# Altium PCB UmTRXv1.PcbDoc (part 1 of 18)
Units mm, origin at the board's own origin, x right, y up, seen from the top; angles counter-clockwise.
Board outline 172 x 113 mm, 6 copper layers (Top Layer, GND, MidLayer1, Mid-Layer 2, InternalPlane2, Bottom Layer); 766 components, 613 nets, 3008 pads, 1360 vias.
Unrouted connection lines stored in the file: 2.
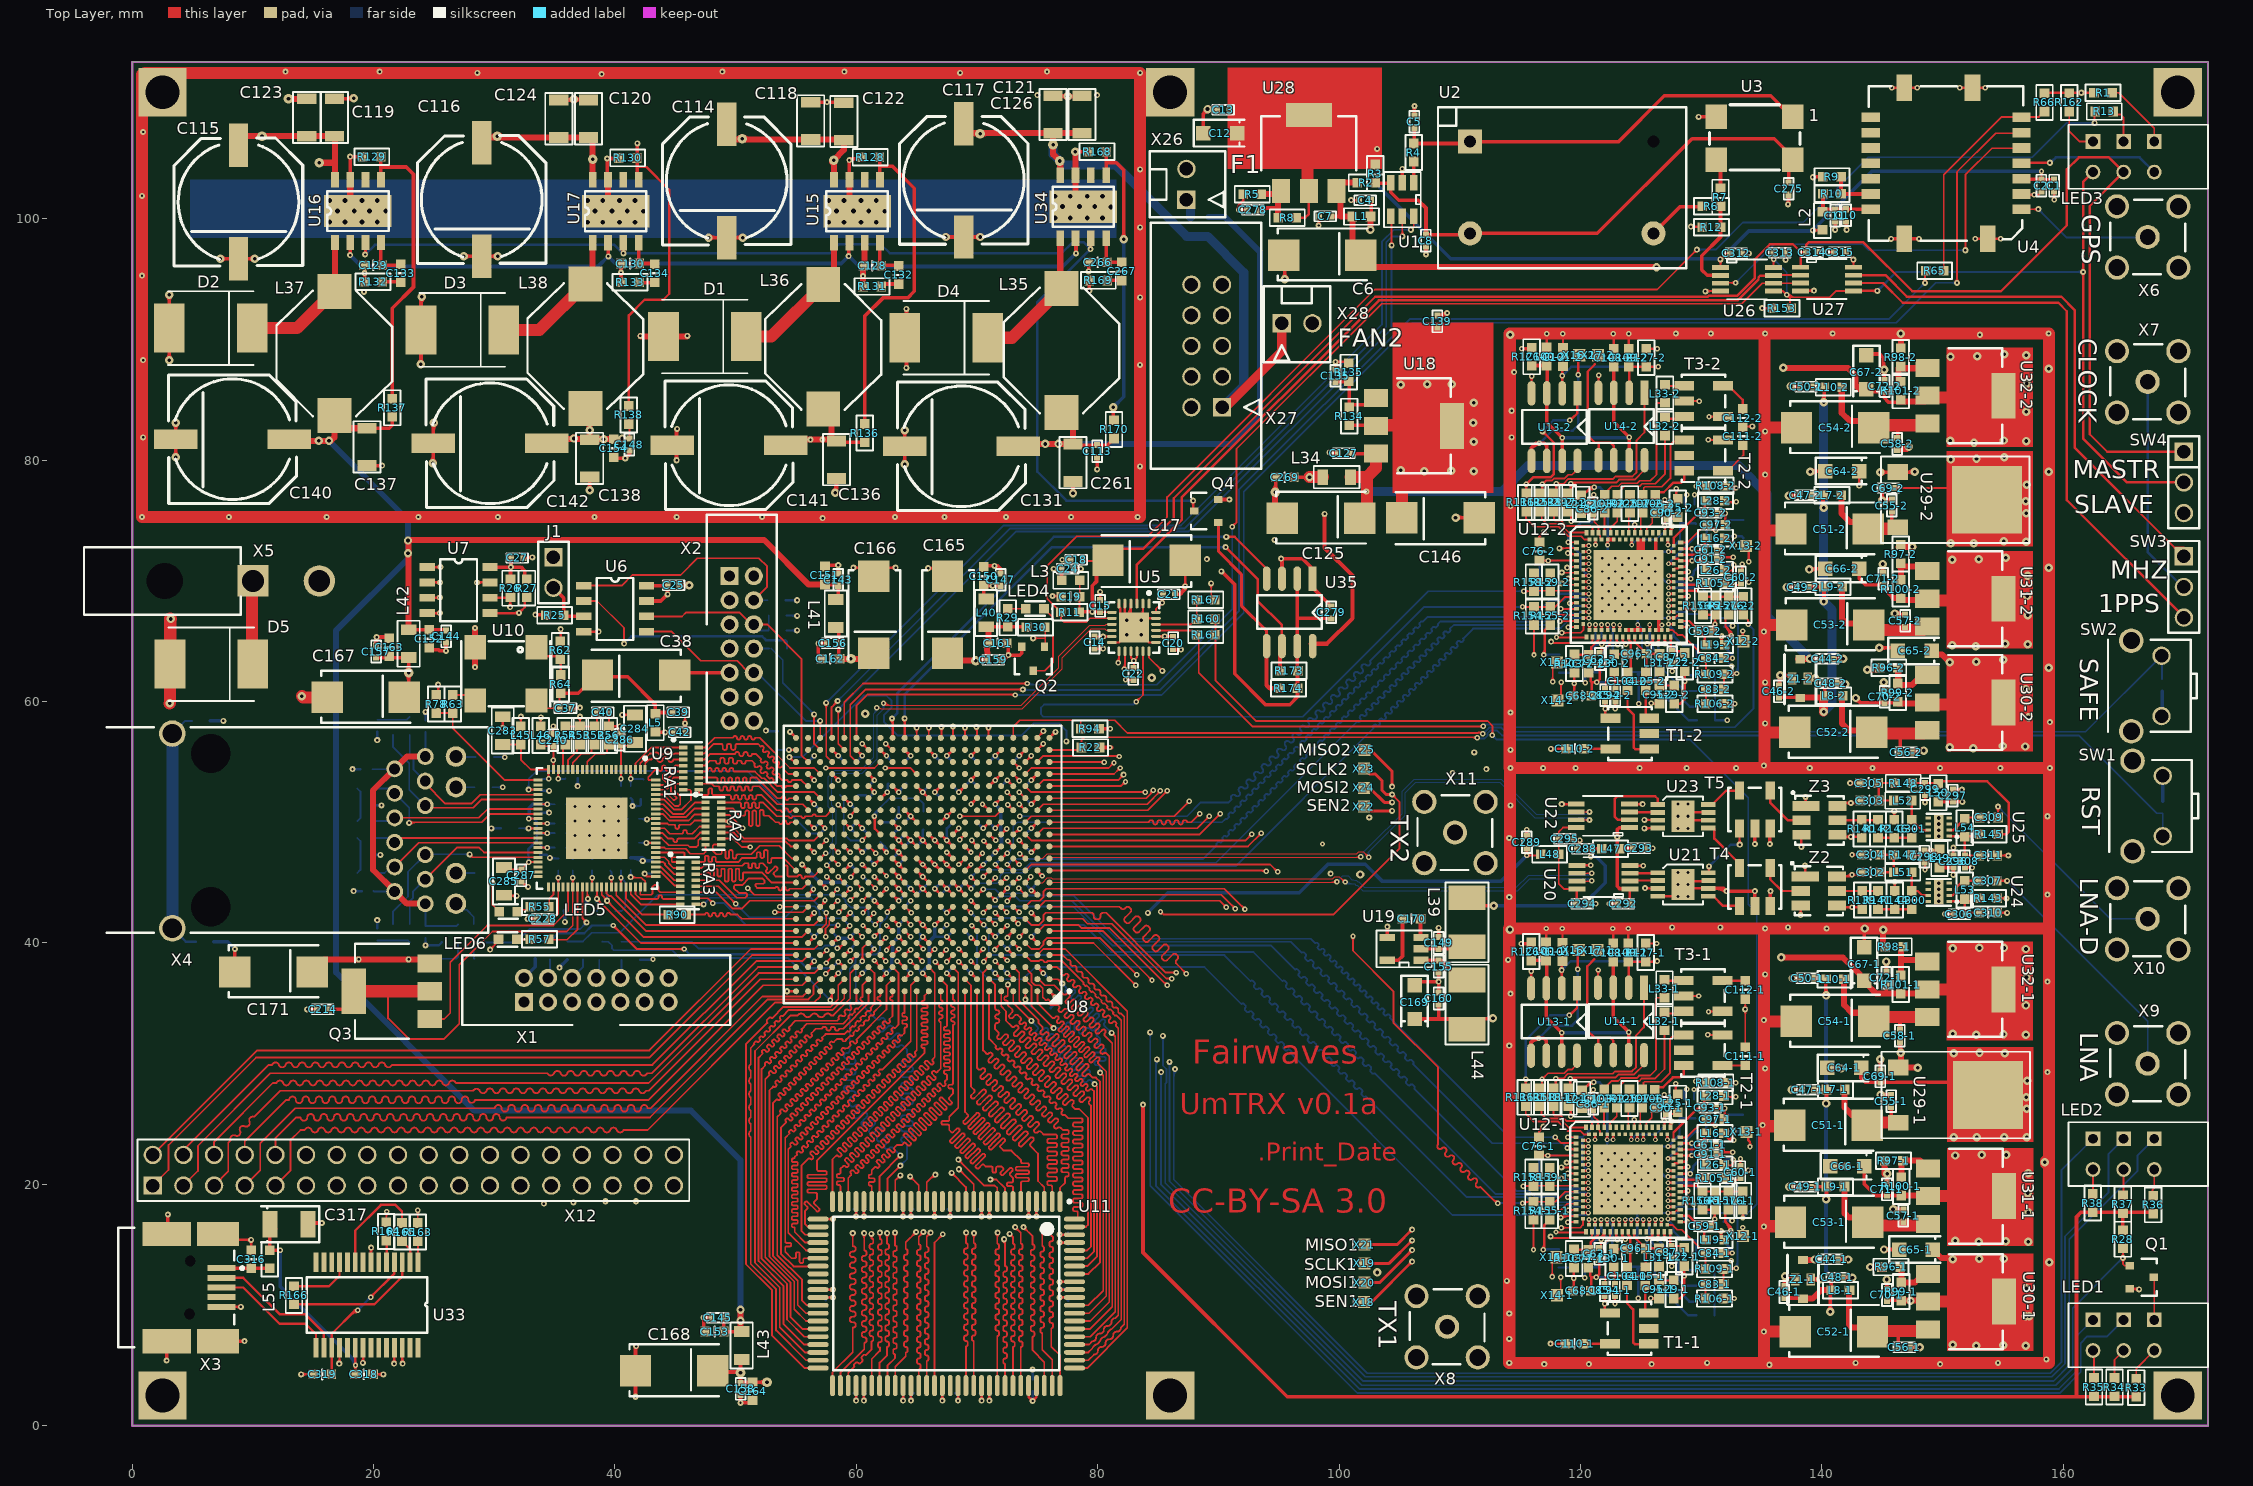
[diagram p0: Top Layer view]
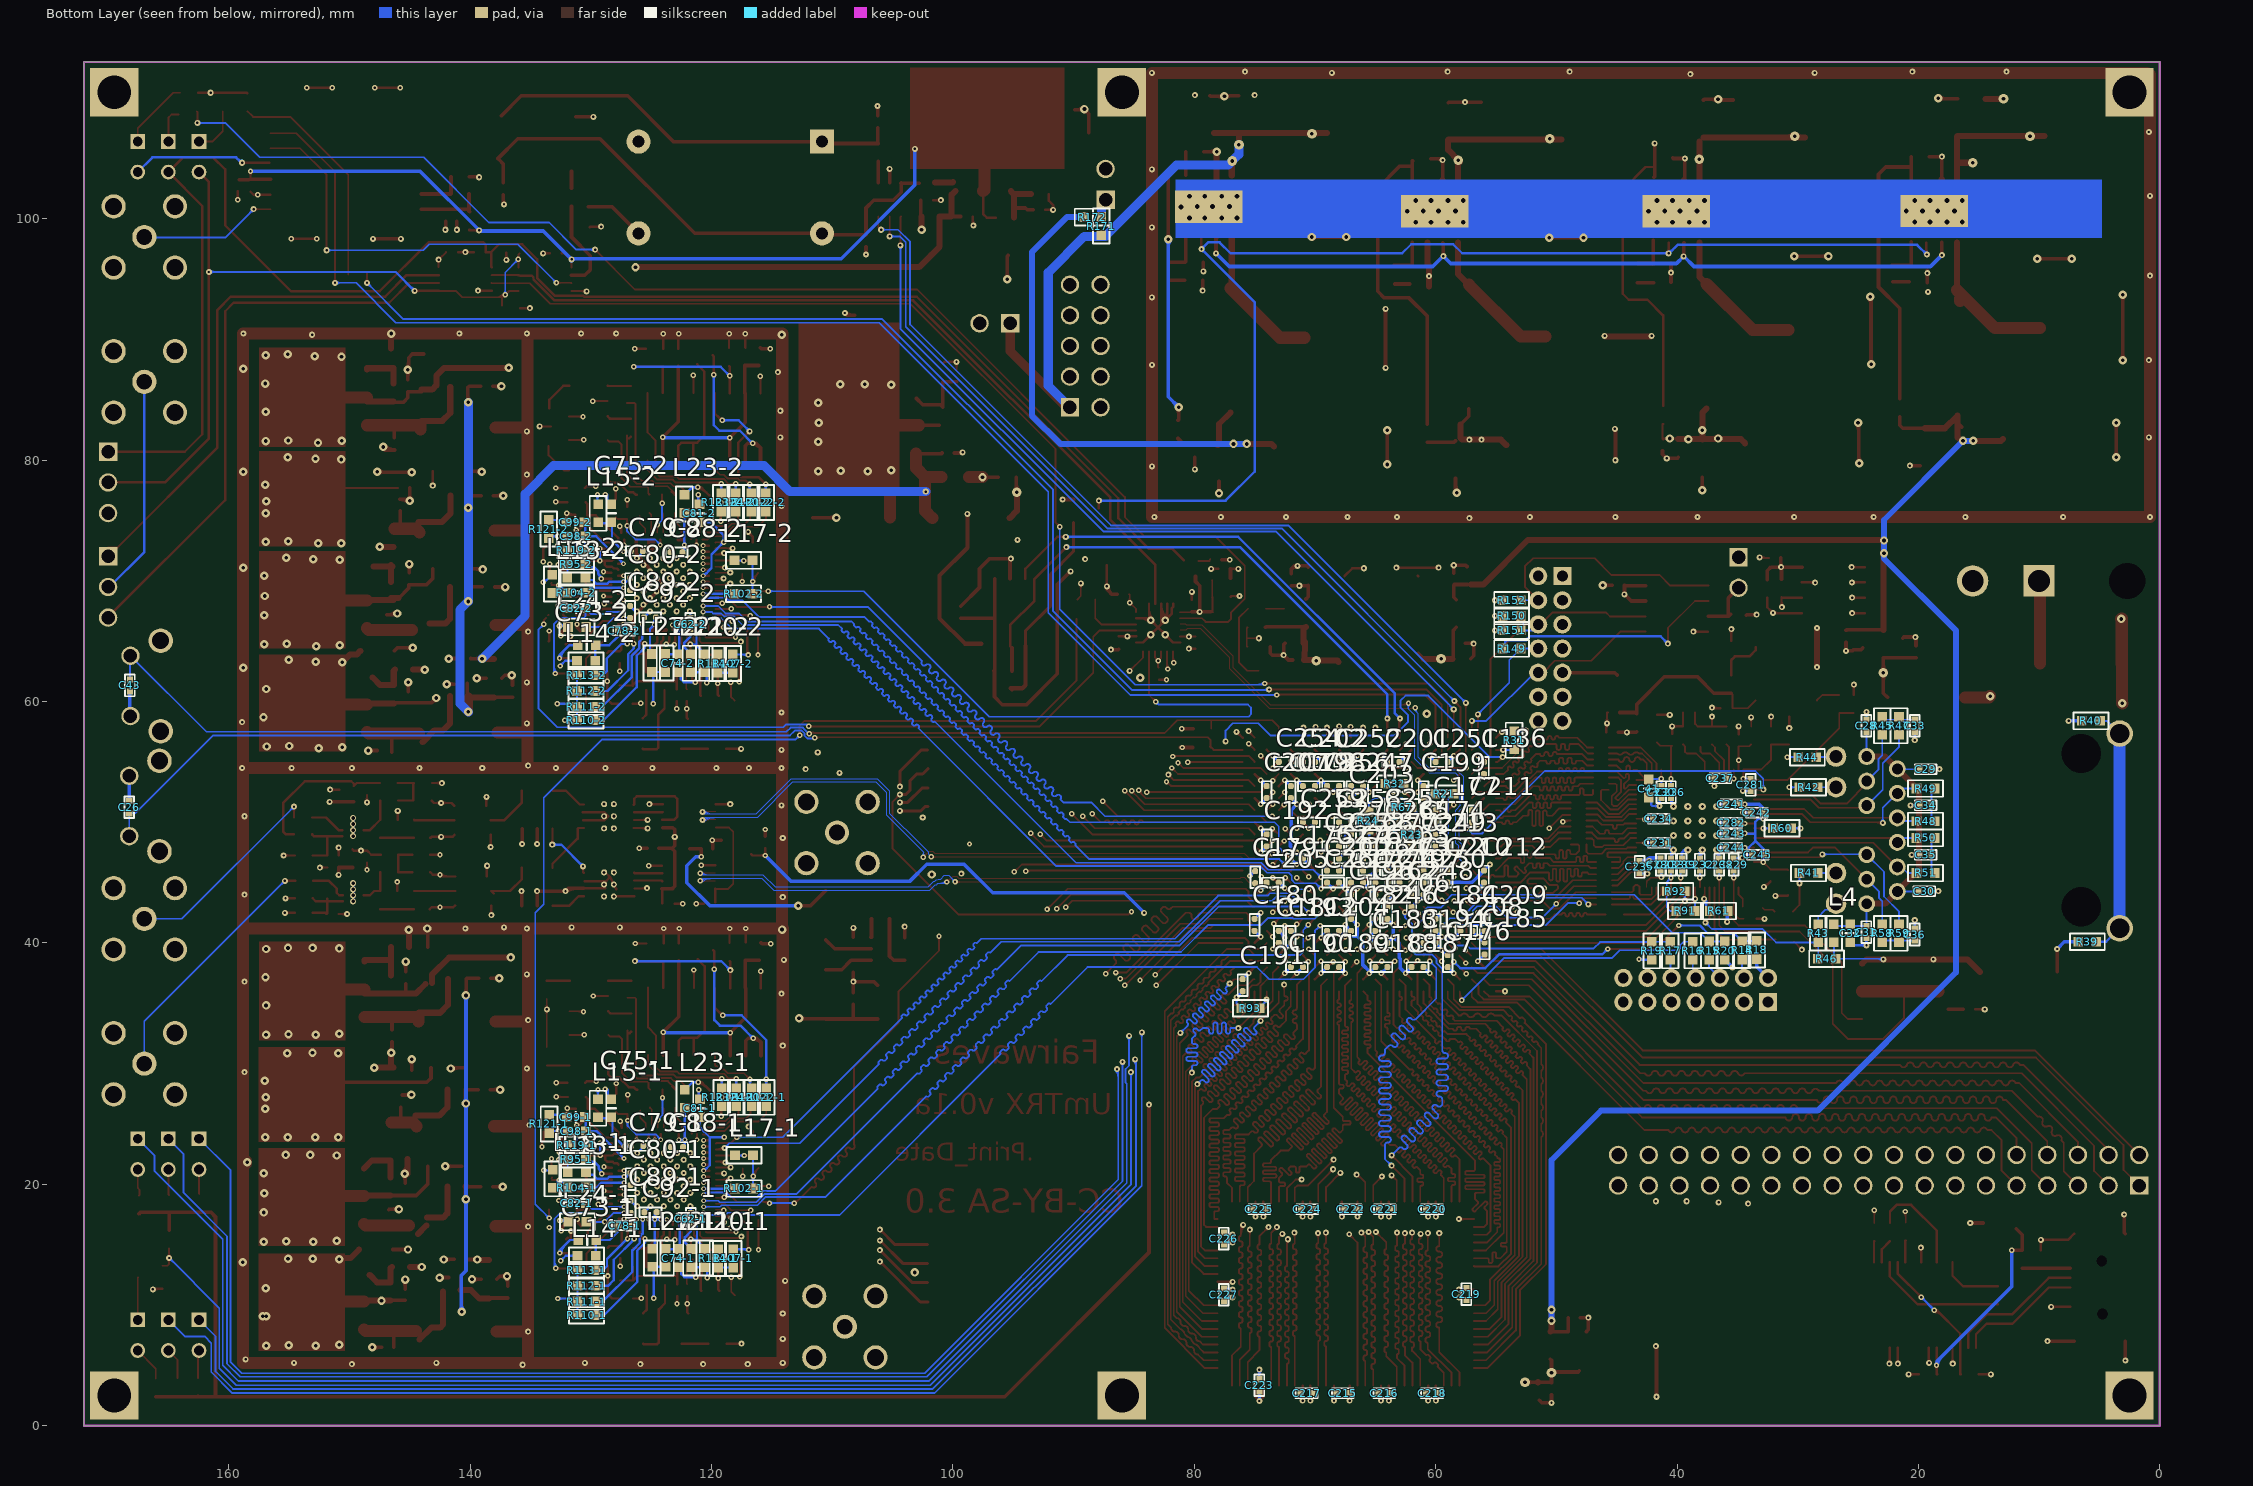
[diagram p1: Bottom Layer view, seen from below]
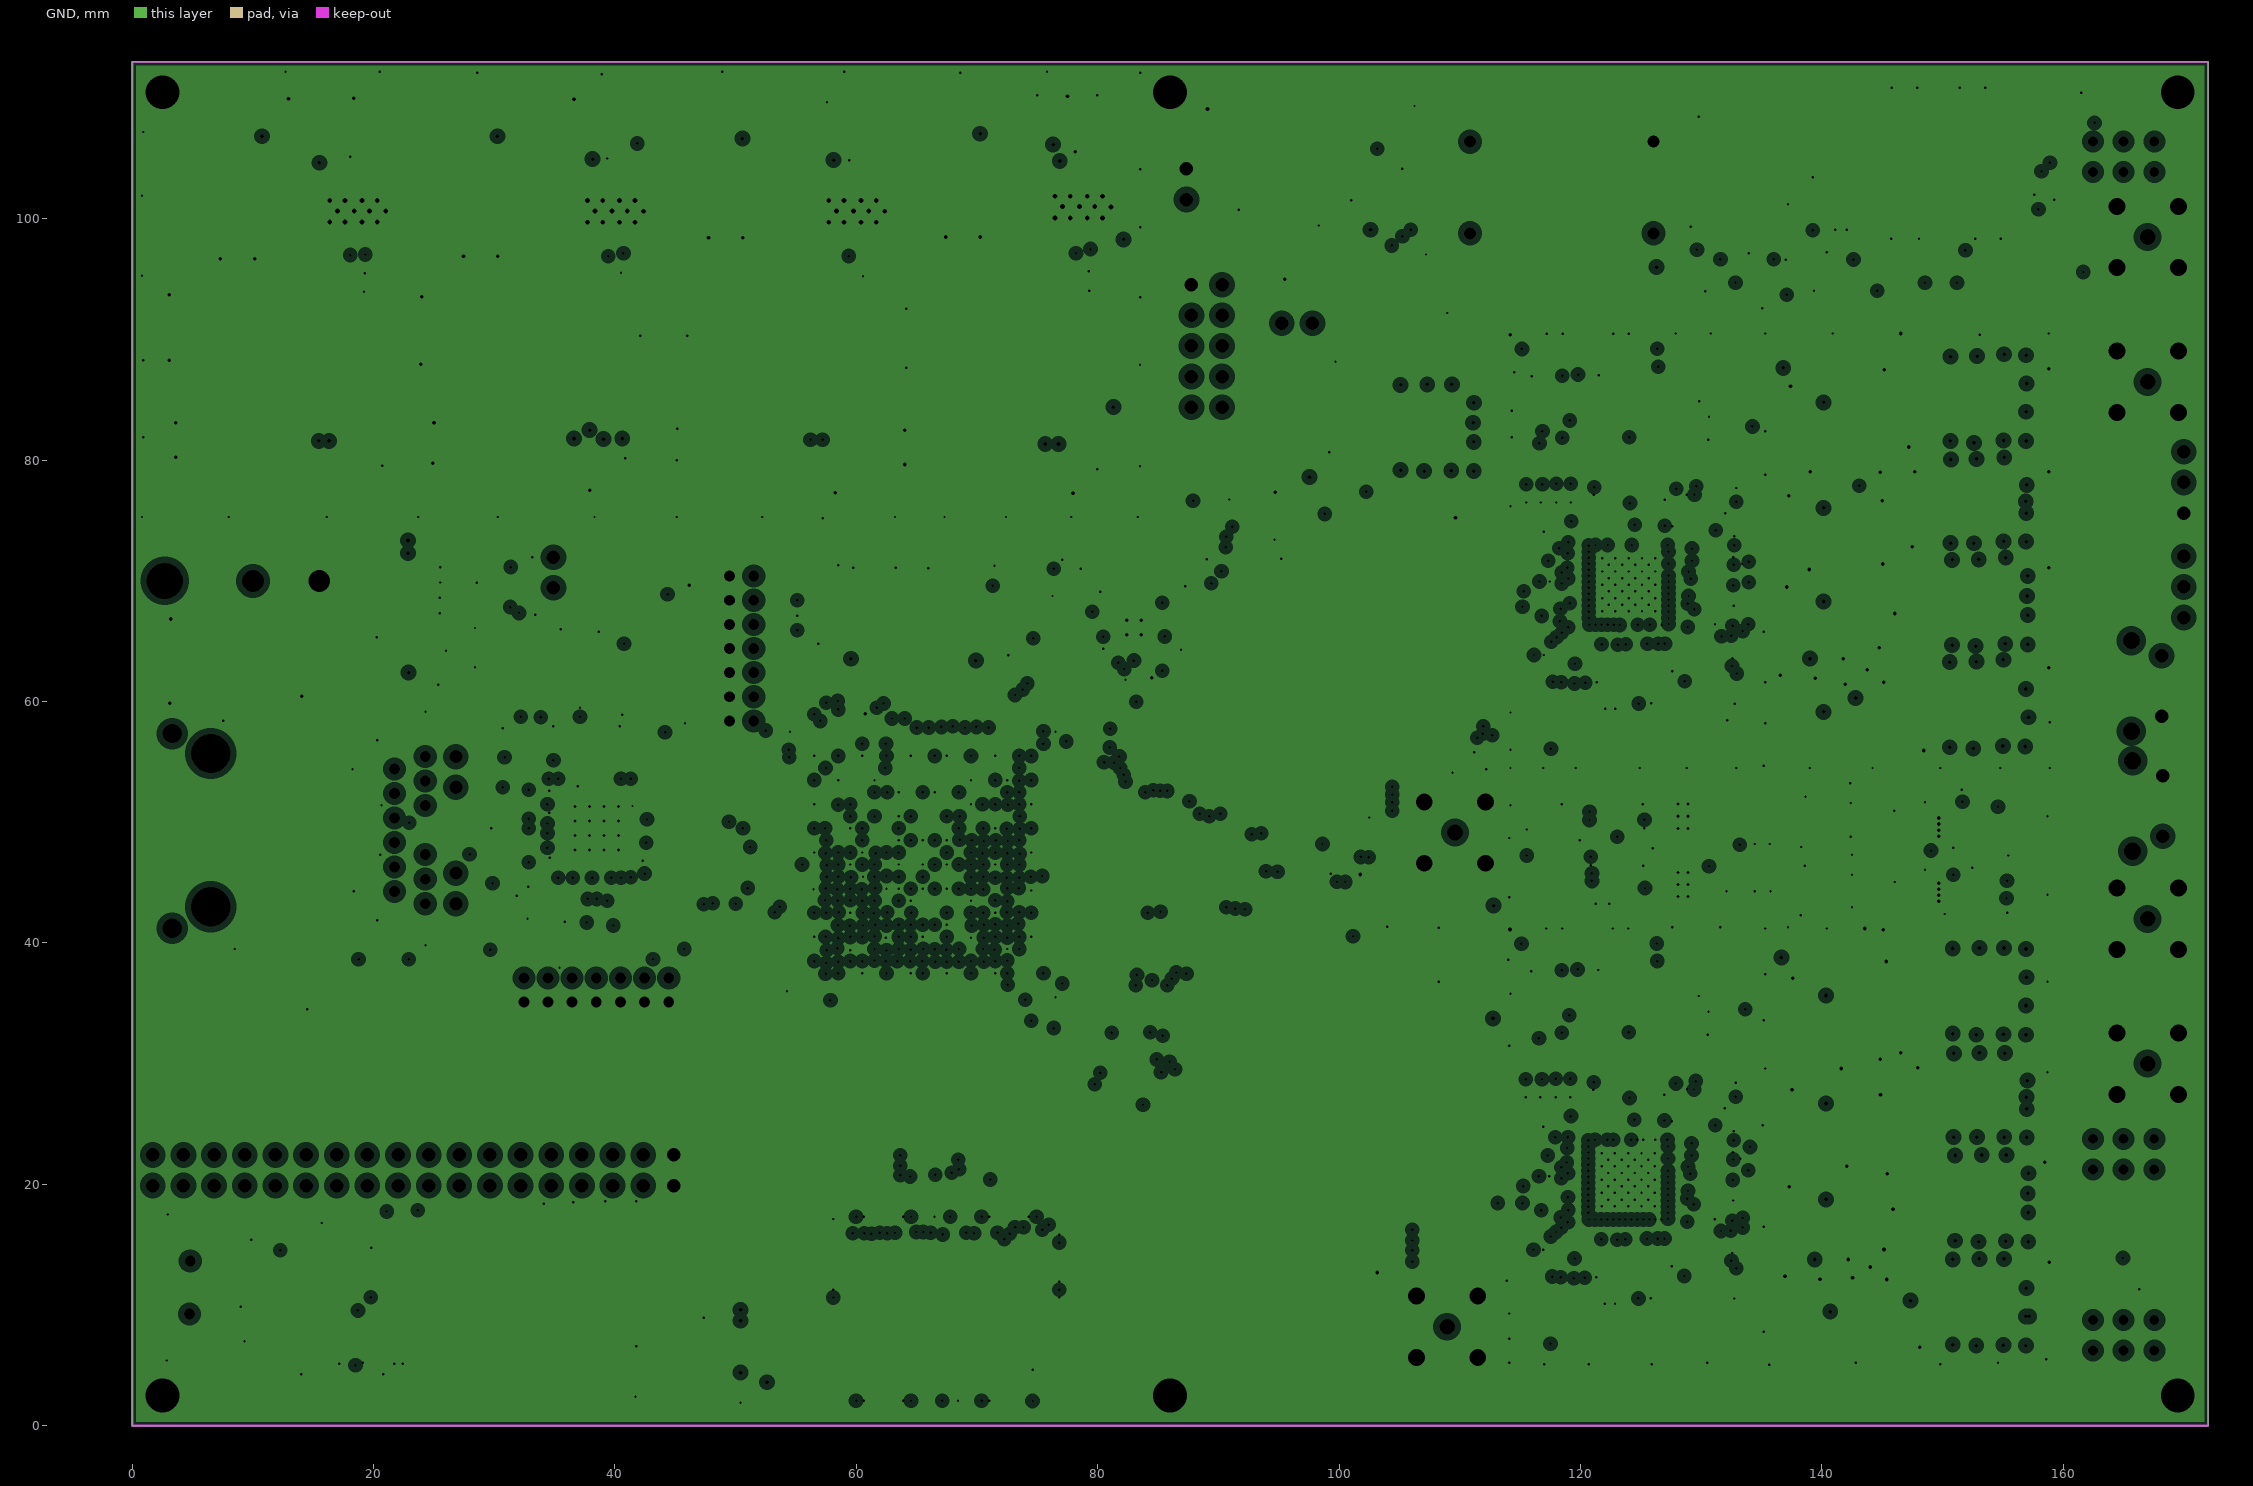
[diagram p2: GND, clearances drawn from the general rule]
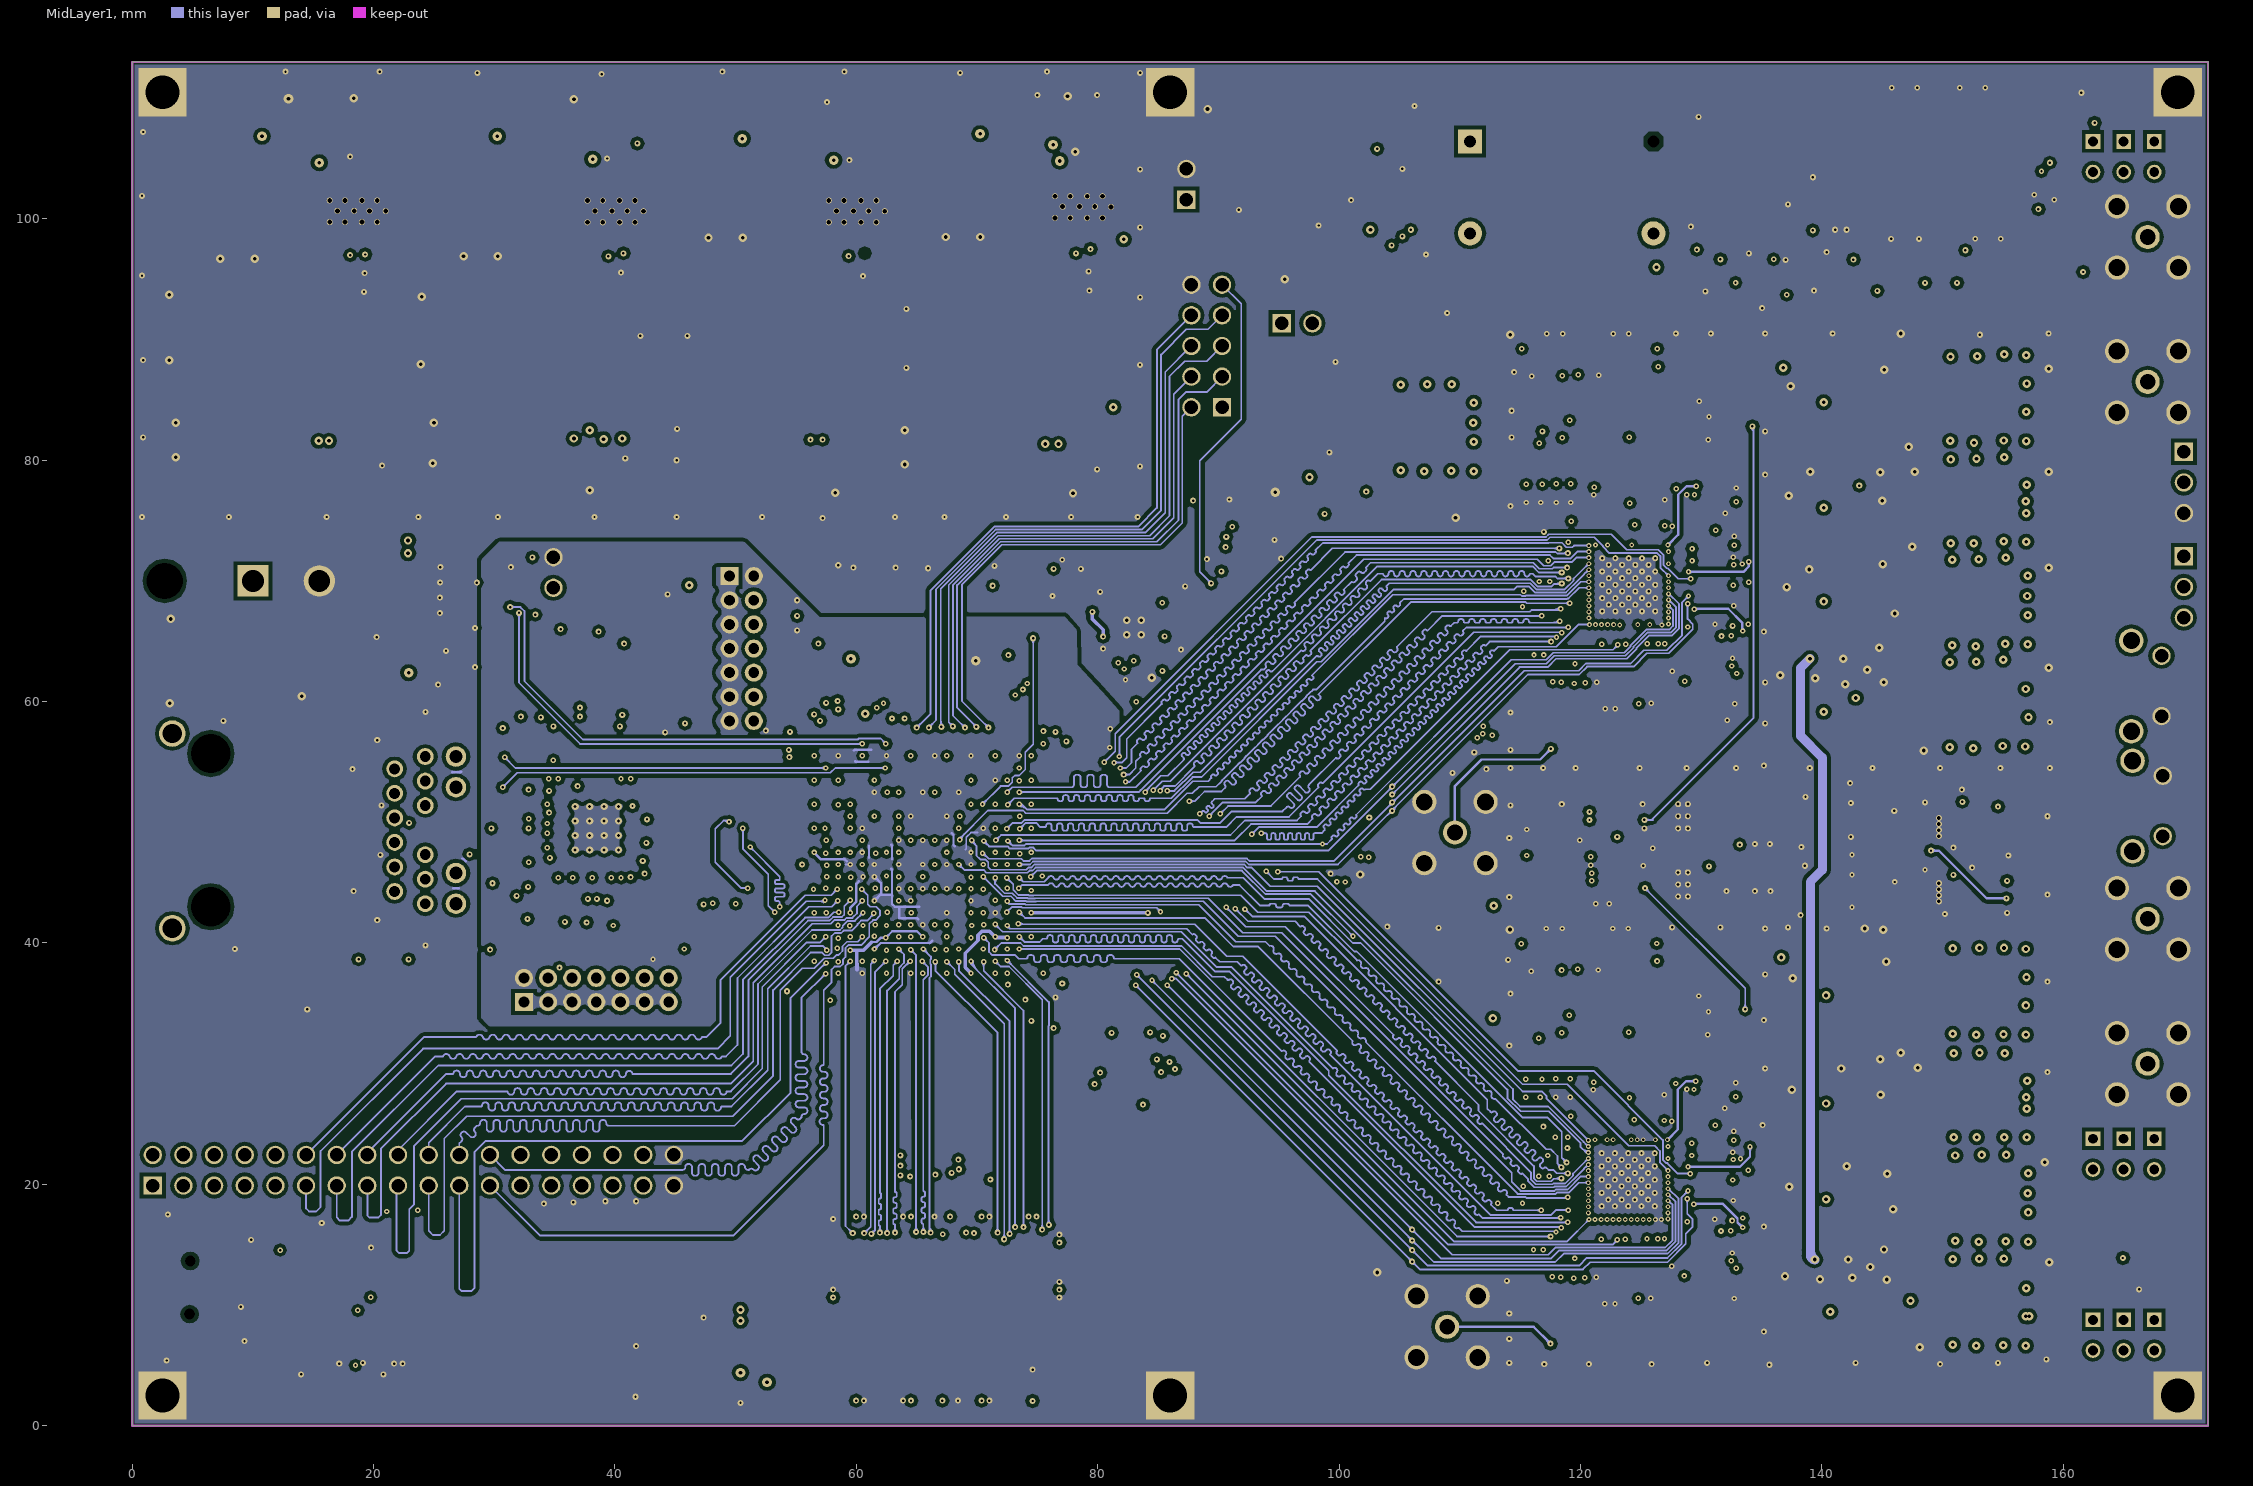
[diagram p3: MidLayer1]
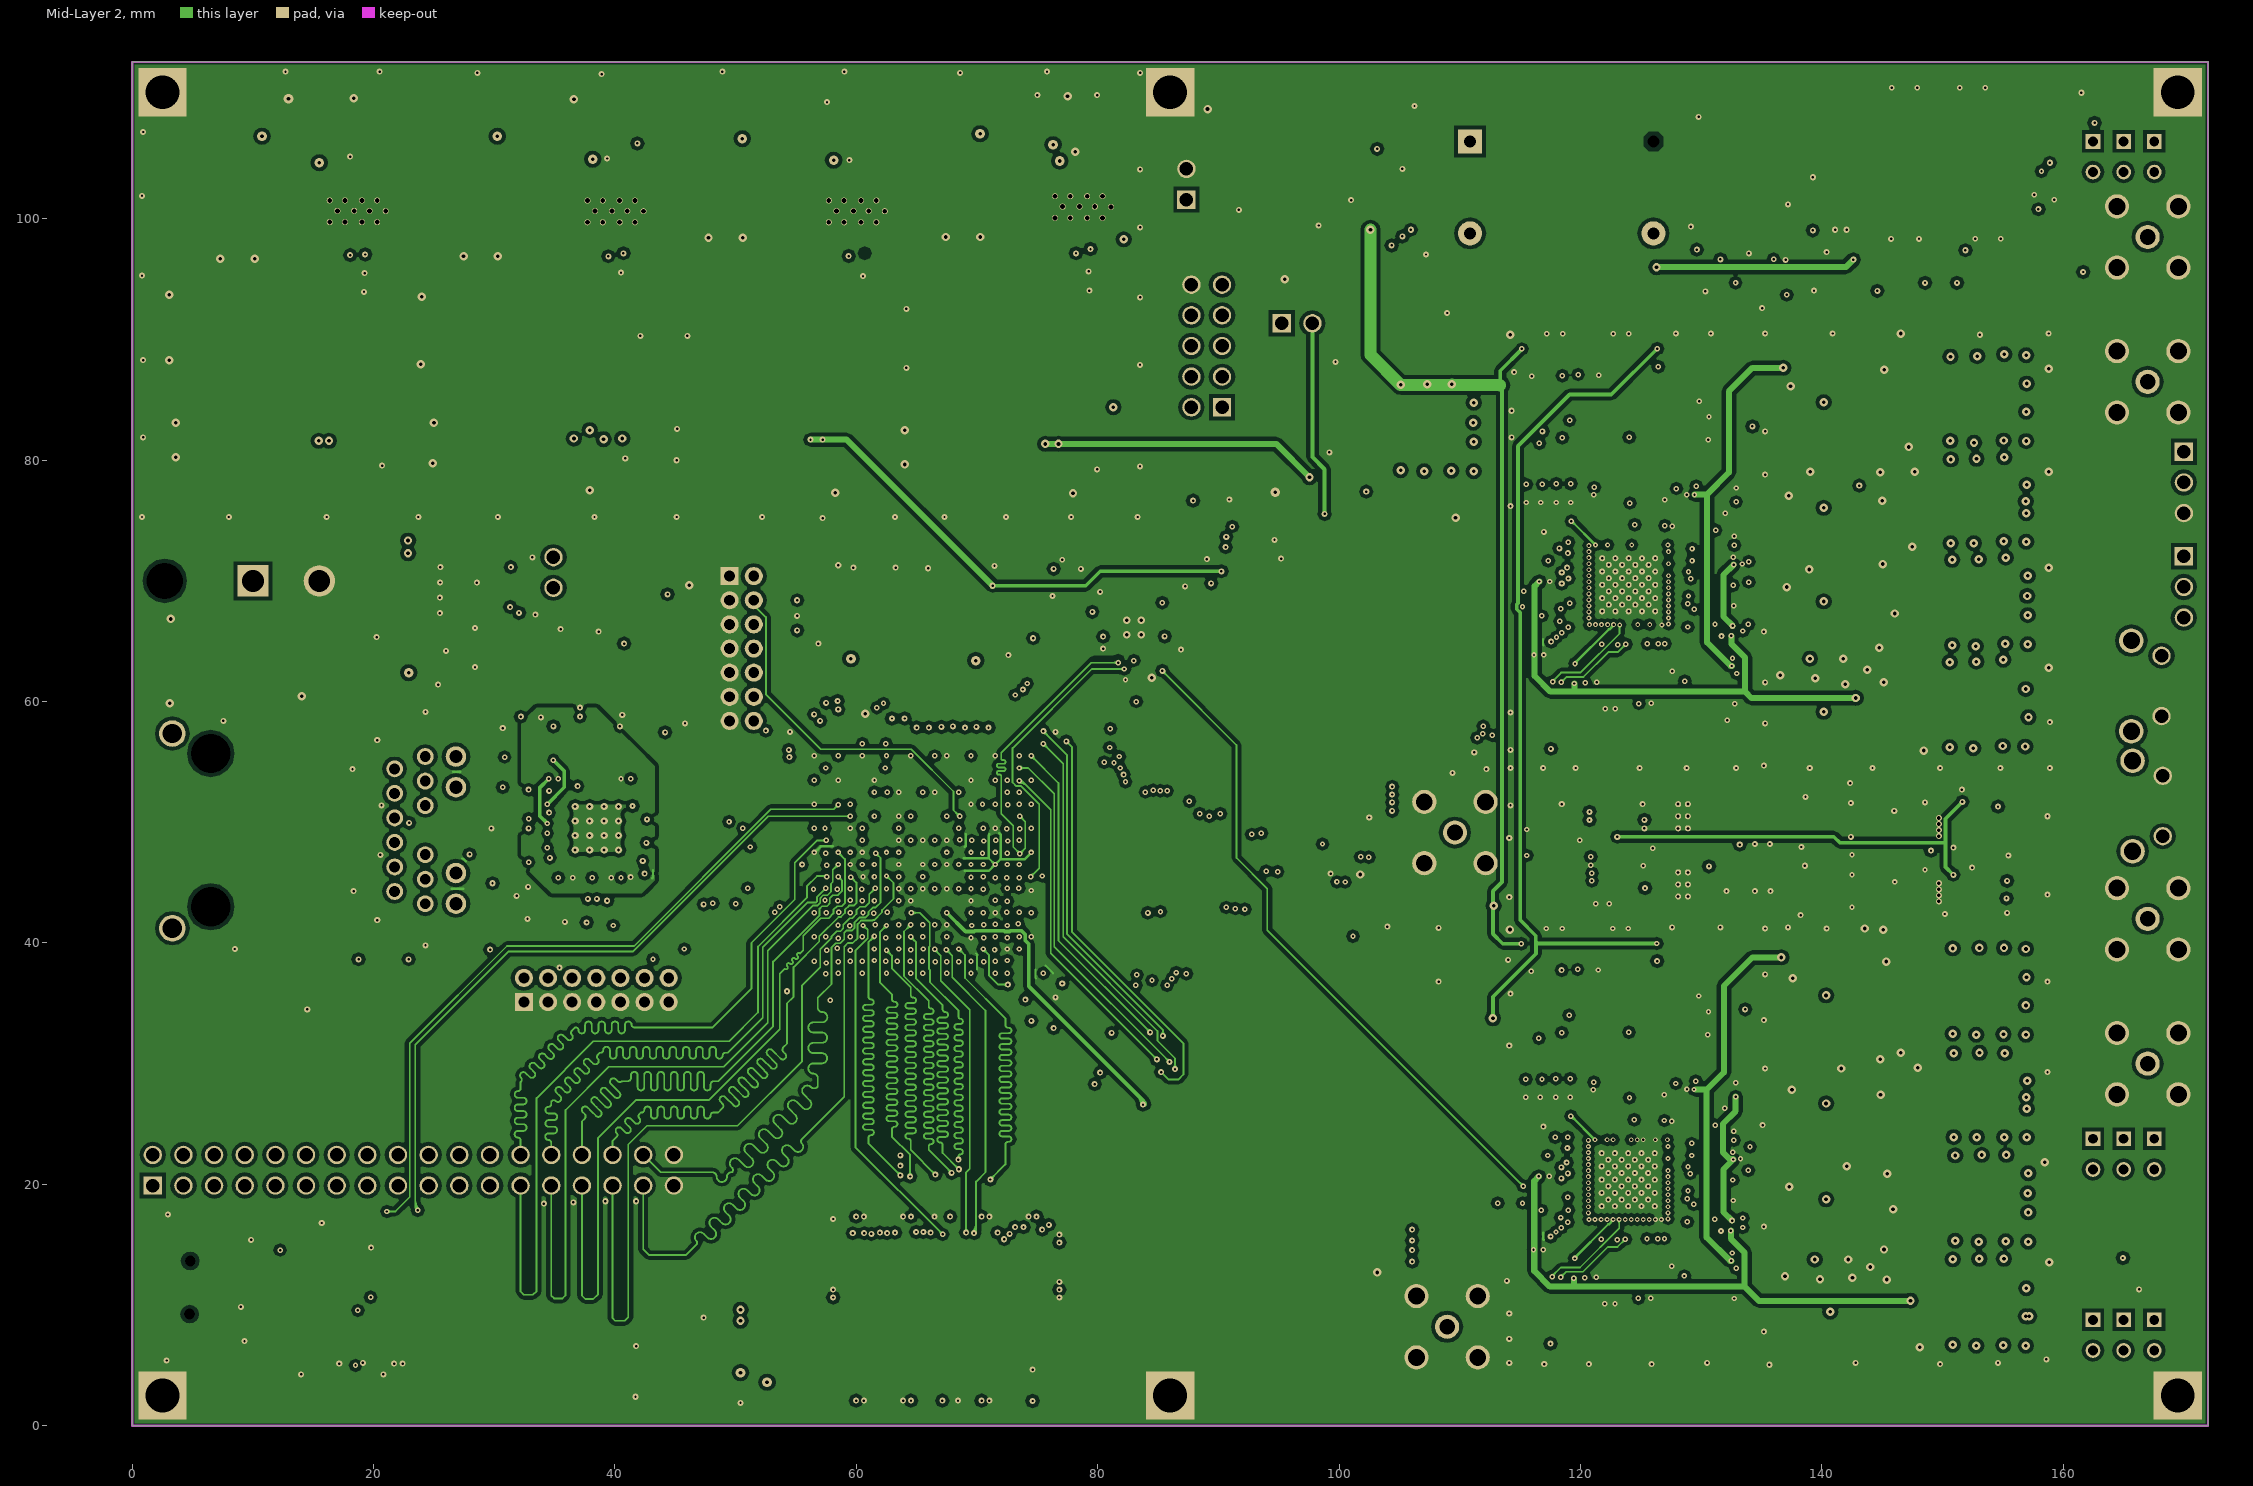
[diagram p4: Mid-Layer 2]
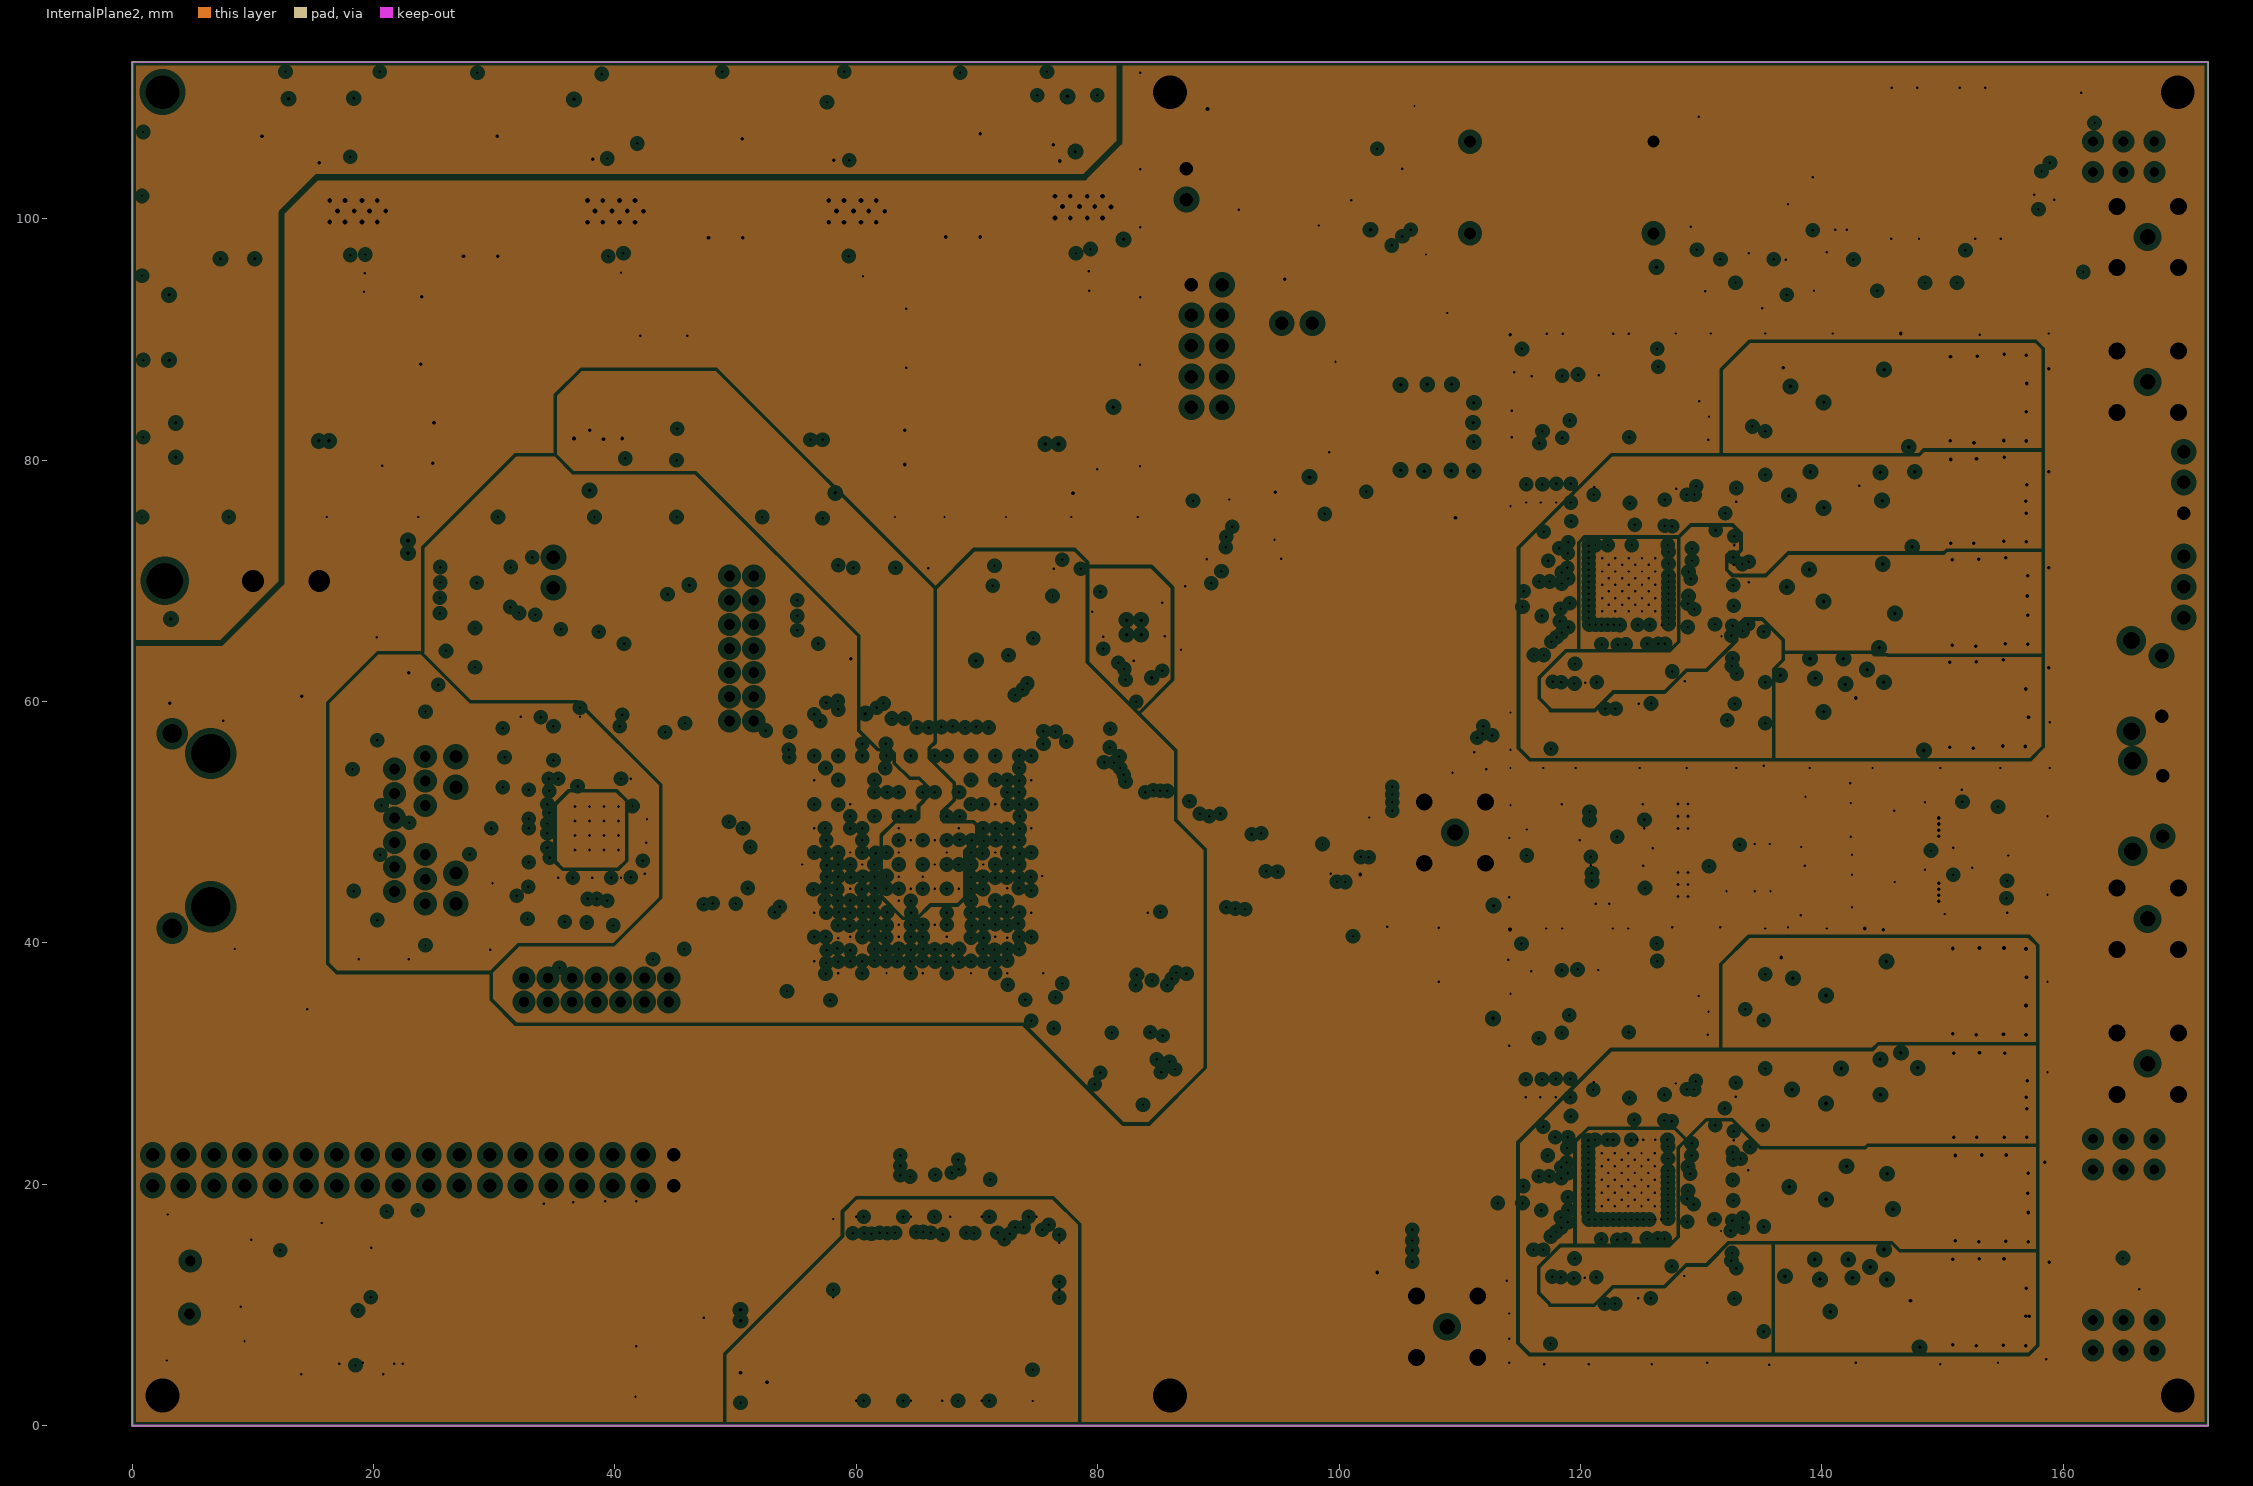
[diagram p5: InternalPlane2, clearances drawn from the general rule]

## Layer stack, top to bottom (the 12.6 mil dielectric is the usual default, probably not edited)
Top Layer: signal copper 0.0356
Dielectric: core 0.32, FR-4, Dk 4.8
GND: plane copper 0.0356, net GND
Dielectric: prepreg 0.32, FR-4, Dk 4.8
MidLayer1: signal copper 0.0356
Dielectric: core 0.32, FR-4, Dk 4.8
Mid-Layer 2: signal copper 0.0356
Dielectric: prepreg 0.32, FR-4, Dk 4.8
InternalPlane2: plane copper 0.0356, net (Multiple Nets)
Dielectric: core 0.32, FR-4, Dk 4.8
Bottom Layer: signal copper 0.0356

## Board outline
0,0 0,113 172,113 172,0

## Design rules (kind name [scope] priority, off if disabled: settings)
Clearance Clearance_8 [(IsPad AND HasFootprint('FBGA484'))] p1: gap=0.1
Clearance Clearance_6 [(IsPad AND HasFootprint('DQFN120(9x9/0.5mm)'))] p2: gap=0.1
Clearance Clearance_7 [(IsPad AND HasFootprint('QFN-84(10x10/0/4mm)with_pad', 'QFN-24(4x4/0/5mm) with Pad'))] p3: gap=0.15
Clearance Clearance_5 [All vs OnLayer('Keep-Out Layer')] p4: gap=0.1
Clearance Clearance_4 [InPoly vs InComponent('Z7*','Z8*','Z1','Z2','Z3','Z4')] p5: gap=0.25
Clearance Clearance_3 [(HasFootprint('CP-24-2', 'LMS6002'))] p6: gap=0.2
Clearance Clearance_2 [OnLayer('Top Layer') and InPoly] p7: gap=0.5
Clearance Clearance_1 [OnLayer('Bottom Layer') and InPoly] p8: gap=0.5
Clearance Clearance_9 [InPoly] p9: gap=0.3
Clearance [All] p10: gap=0.1
ComponentClearance [All] p1 off: gap=0.254 collisioncheckmode=3 verticalgap=0.254 showdistances=FALSE
DiffPairsRouting [All] p1: maxlimit=0.18 minlimit=0.18 mostfreqgap=0.18 maxuncoupledlength=10
FabricationTestPointUsage TestPointUsage [All] p1: valid=0 allowmultiple=FALSE
FabricationTestpoint Testpoint [All] p1: side=3 testpointundercomponent=TRUE minsize=1.016 maxsize=2.54 preferedsize=1.524 minholesize=0 maxholesize=1.016 preferedholesize=0.813 testpointgrid=0.025 allowsidetop=TRUE allowsidebottom=TRUE usegrid=TRUE gridtolerance=0
Height [All] p1 off: minheight=0 maxheight=25.4 prefheight=12.7
HoleSize [All] p1: absolutevalues=TRUE maxlimit=4 minlimit=0.2 maxpercent=80.000 minpercent=20.000
HoleToHoleClearance [All] p1 off: gap=0.5 allowstackedmicrovias=TRUE
Length Length_6 [InNetClass('RX1') Or InNetClass('RX2')] p1 off: maxlimit=63.4 minlimit=62.4
Length Length_7 [InNetClass('Debug')] p2 off: maxlimit=62.6 minlimit=61.6
Length Length_5 [InNetClass('TX1') Or InNetClass('TX2')] p3 off: maxlimit=67.6 minlimit=66.6
Length Length_4 [InNet('GMII_RXD0') or InNet('GMII_RXD1') or InNet('GMII_RXD2') or InNet('GMII_RXD3')] p4 off: maxlimit=13.3 minlimit=12.8
Length Length_3 [InNetClass('GMII_RX')] p5 off: maxlimit=13.4 minlimit=12.9
Length Length_2 [InNetClass('GMII_TX')] p6 off: maxlimit=12.8 minlimit=12.3
Length Length_1 [InNetClass('ResArray')] p7 off: maxlimit=5.05 minlimit=4.5
Length [InNetClass('RAM')] p8 off: maxlimit=41.8 minlimit=40.8
MinimumSolderMaskSliver [All] p1: minsoldermaskwidth=0.095
PasteMaskExpansion [All] p1: expansion=0.05
PlaneClearance [OnLayer('Bottom Layer')] p1: clearance=0.25
PlaneConnect PlaneConnect_3 [IsPad AND (HasFootprint('DQFN120(9x9/0.5mm)') Or HasFootprint('SOIC8 - BackGND - 0.4mm dia') Or HasFootprint('MS8G'))] p1: planeconnectstyle=Direct reliefexpansion=0.508 reliefentries=4 reliefconductorwidth=0.254 reliefairgap=0.254
PlaneConnect PlaneConnect_1 [IsVia] p2: planeconnectstyle=Direct reliefexpansion=0.508 reliefentries=4 reliefconductorwidth=0.254 reliefairgap=0.254
PlaneConnect [InNet('GND')] p3: planeconnectstyle=Relief reliefexpansion=0.5 reliefentries=4 reliefconductorwidth=0.5 reliefairgap=0.25
PlaneConnect PlaneConnect_2 [All] p4: planeconnectstyle=Relief reliefexpansion=0.508 reliefentries=4 reliefconductorwidth=0.254 reliefairgap=0.254
PolygonConnect PolygonConnect_1 [IsVia] p1: connectstyle=Direct reliefconductorwidth=0.254 reliefentries=4 polygonreliefangle="90 Angle"
PolygonConnect PolygonConnect_4 [InComponent('Z1','Z2','Z3','Z4','Z7*','Z8*')] p2: connectstyle=Relief reliefconductorwidth=0.5 reliefentries=4 polygonreliefangle="90 Angle"
PolygonConnect PolygonConnect_3 [(InComponent('d*'))] p3: connectstyle=Direct reliefconductorwidth=0.254 reliefentries=4 polygonreliefangle="90 Angle"
PolygonConnect PolygonConnect_2 [(HasFootprint('BH-20'))] p4: connectstyle=Relief reliefconductorwidth=0.7 reliefentries=4 polygonreliefangle="90 Angle"
PolygonConnect PolygonConnect_5 [HasPad('Free-0')] p5: connectstyle=Direct reliefconductorwidth=0.254 reliefentries=4 polygonreliefangle="90 Angle"
PolygonConnect [All] p6: connectstyle=Direct reliefconductorwidth=0.5 reliefentries=4 polygonreliefangle="90 Angle"
RoomDefinition LMS-b [InComponentClass('LMS-b')] p1: confinementstyle=ConfineIn formatcopy=TRUE lockcomponents=FALSE outline 113,52.5 160,52.5 160,91.5 113,91.5
RoomDefinition LMS-a [InComponentClass('LMS-a')] p2: confinementstyle=ConfineIn formatcopy=TRUE lockcomponents=FALSE outline 112.961,3.208 159.961,3.208 159.961,42.208 112.961,42.208
RoutingVias [All] p1: holewidth=0.5 width=1 viastyle="Through Hole" minholewidth=0.2 minwidth=0.4 maxholewidth=0.8 maxwidth=1.2
SilkToSilkClearance [All] p1: silktosilkclearance=0.1
SilkscreenOverComponentPads [All] p1: minsilkscreentomaskgap=0.1
SolderMaskExpansion [All] p1: expansion=0.075
Width Width_1 [IsDifferentialPair] p1: maxlimit=0.1 minlimit=0.1 preferedwidth=0.1
Width [All] p2: maxlimit=2 minlimit=0.1 preferedwidth=0.25
15 further rules are at their usual default settings.

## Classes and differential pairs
net class Debug: DEBUG0 DEBUG1 DEBUG2 DEBUG3 DEBUG4 DEBUG5 DEBUG6 DEBUG7 DEBUG8 DEBUG9 DEBUG10 DEBUG11 DEBUG12 DEBUG13 DEBUG14 DEBUG15 DEBUG16 DEBUG17 DEBUG18 DEBUG19 DEBUG20 DEBUG21 DEBUG22 DEBUG23 DEBUG24 DEBUG25 DEBUG26 DEBUG27 DEBUG28 DEBUG29 DEBUG30 DEBUG31 DEBUG_CLK0 DEBUG_CLK1
component class LNA_DIV: C288 C289 C292 C293 C294 C295 C296 C297 C298 C299 C300 C301 C302 C303 C304 C305 C306 C307 C308 C309 C310 C311 L47 L48 L49 L50 L51 L52 L53 L54 R123 R139 R140 R141 R142 R143 R144 R145 R146 R147 R148 T4 T5 U20 U21 U22 U23 U24 U25 Z2 Z3
component class FPGA_RAM: R93 U8 U11 X12 X18 X19 X20 X21 X22 X23 X24 X25
component class GBEthernet: C28 C29 C30 C31 C32 C33 C34 C35 C36 C37 C38 C39 C40 C41 C42 L4 L5 LED5 LED6 R39 R40 R41 R42 R43 R44 R45 R46 R47 R48 R49 R50 R51 R52 R53 R54 R55 R56 R57 R58 R59 R60 R61 R62 R63 R64 R78 R90 R91 R92 RA1 RA2 RA3 U9 U10 X4
component class EEpromConfig: C25 C26 C27 C43 C316 C317 C318 C319 J1 L55 LED1 LED2 LED4 Q1 Q2 R14 R15 R16 R17 R18 R19 R20 R21 R22 R23 R24 R25 R26 R27 R28 R29 R30 R31 R32 R33 R34 R35 R36 R37 R38 R67 R94 R149 R150 R151 R152 R163 R164 R165 R166 SW1 SW2 U6 U7 U33 X1 X2 X3 X26
component class Clocking: C1 C2 C4 C5 C6 C7 C8 C10 C11 C12 C13 C14 C15 C17 C18 C19 C20 C21 C22 C24 C275 C278 C312 C313 C314 C315 L1 L2 L3 LED3 R1 R2 R3 R4 R5 R6 R7 R8 R9 R10 R11 R12 R13 R65 R66 R153 R160 R161 R162 R167 SW3 SW4 U1 U2 U3 U4 U5 U26 U27 U28
component class Total: X6 X7 X8 X9 X10 X11
component class PwrAndBias: C113 C114 C115 C116 C117 C118 C119 C120 C121 C122 C123 C124 C125 C126 C127 C128 C129 C130 C131 C132 C133 C134 C135 C136 C137 C138 C139 C140 C141 C142 C143 C144 C145 C146 C147 C148 C149 C150 C151 C152 C153 C154 C155 C156 C157 C158 C159 C160 C161 C162 C163 C164 C165 C166 C167 C168 C169 C170 C171 C172 C174 C175 C176 C177 C178 C179 C180 C181 C182 C183 C184 C185 C186 C187 C188 C189 C190 C191 C192 C193 C194 C196 C197 C198 C199 C200 C201 C202 C203 C204 C205 C206 C207 C208 C209 C210 C211 C212 C213 C214 C215 C216 C217 C218 C219 C220 C221 C222 C223 C224 C225 C226 C227 C228 C229 C230 C231 C232 C233 C234 C235 C236 C237 C238 C239 C240 C241 C242 C243 C244 C245 C246 C247 C248 C249 C250 C251 C252 C254 C255 C256 C257 C258 C259 C260 C261 C262 C263 C264 C265 C266 C267 C268 C269 C270 C271 C272 C273 C274 C276 C277 C279 C280 C281 C282 C283 C284 C285 C286 C287 D1 D2 D3 D4 D5 L34 L35 L36 L37 L38 L39 L40 L41 L42 L43 L44 L45 L46 Q3 Q4 R128 R129 R130 R131 R132 R133 R134 R135 R136 R137 R138 R168 R169 R170 R171 R172 R173 R174 U15 U16 U17 U18 U19 U34 U35 X5 X27 X28
component class LMS-a: C44-1 C45-1 C46-1 C47-1 C48-1 C49-1 C50-1 C51-1 C52-1 C53-1 C54-1 C55-1 C56-1 C56a C57-1 C57a C58-1 C58a C59-1 C59a C60-1 C60a C61-1 C61a C62-1 C62a C63-1 C63a C64-1 C64a C65-1 C65a C66-1 C66a C67-1 C67a C68-1 C68a C69-1 C69a C70-1 C70a C71-1 C71a C72-1 C72a C73-1 C73a C74-1 C74a C75-1 C75a C76-1 C76a C77-1 C77a C78-1 C78a C79-1 C79a C80-1 C80a C81-1 C82-1 C83-1 C84-1 C85-1 C86-1 C87-1 C88-1 C89-1 C90-1 C91-1 C92-1 C93-1 C94-1 C95-1 C96-1 C97-1 C98-1 C99-1 C100-1 C101-1 C102-1 C103-1 C104-1 C105-1 C106-1 C107-1 C108-1 C109-1 C110-1 C111-1 C112-1 D2a D3a D4a D5a L6-1 L7-1 L8-1 L9-1 L10-1 L11-1 L12-1 L12a L13-1 L13a L14-1 L14a L15-1 L15a L16-1 L16a L17-1 L18-1 L19-1 L20-1 L21-1 L22-1 L23-1 L24-1 L25-1 L26-1 L27-1 L28-1 L29-1 L30-1 L31-1 L32-1 L33-1 R95-1 R96-1 R97-1 R97a R98-1 R98a R99-1 R99a R100-1 R100a R101-1 R101a R102-1 R102a R103-1 R103a R104-1 R105-1 R106-1 R107-1 R108-1 R109-1 R110-1 R111-1 R112-1 R113-1 R114-1 R115-1 R116-1 R117-1 R118-1 R119-1 R120-1 R121-1 R122-1 R123-1 R124-1 R125-1 R126-1 R127-1 R154-1 R155-1 R156-1 R157-1 R158-1 R159-1 T1-1 T2-1 T3-1 U12-1 U13' U13-1 U14-1 U16a U29-1 U30-1 U31-1 U32-1 X12-1 X12a X13-1 X13a X14-1 X14a X15-1 X15a X16-1 X17-1 Z1-1 Z3a
component class LMS-b: C44-2 C45-2 C46-2 C47-2 C48-2 C49-2 C50-2 C51-2 C52-2 C53-2 C54-2 C55-2 C56-2 C56b C57-2 C57b C58-2 C58b C59-2 C59b C60-2 C60b C61-2 C61b C62-2 C62b C63-2 C63b C64-2 C64b C65-2 C65b C66-2 C66b C67-2 C67b C68-2 C68b C69-2 C69b C70-2 C70b C71-2 C71b C72-2 C72b C73-2 C73b C74-2 C74b C75-2 C75b C76-2 C76b C77-2 C77b C78-2 C78b C79-2 C79b C80-2 C80b C81-2 C82-2 C83-2 C84-2 C85-2 C86-2 C87-2 C88-2 C89-2 C90-2 C91-2 C92-2 C93-2 C94-2 C95-2 C96-2 C97-2 C98-2 C99-2 C100-2 C101-2 C102-2 C103-2 C104-2 C105-2 C106-2 C107-2 C108-2 C109-2 C110-2 C111-2 C112-2 D2b D3b D4b D5b L6-2 L7-2 L8-2 L9-2 L10-2 L11-2 L12-2 L12b L13-2 L13b L14-2 L14b L15-2 L15b L16-2 L16b L17-2 L18-2 L19-2 L20-2 L21-2 L22-2 L23-2 L24-2 L25-2 L26-2 L27-2 L28-2 L29-2 L30-2 L31-2 L32-2 L33-2 R95-2 R96-2 R97-2 R97b R98-2 R98b R99-2 R99b R100-2 R100b R101-2 R101b R102-2 R102b R103-2 R103b R104-2 R105-2 R106-2 R107-2 R108-2 R109-2 R110-2 R111-2 R112-2 R113-2 R114-2 R115-2 R116-2 R117-2 R118-2 R119-2 R120-2 R121-2 R122-2 R123-2 R124-2 R125-2 R126-2 R127-2 R154-2 R155-2 R156-2 R157-2 R158-2 R159-2 T1-2 T2-2 T3-2 U12-2 U13'' U13-2 U14-2 U16b U29-2 U30-2 U31-2 U32-2 X12-2 X12b X13-2 X13b X14-2 X14b X15-2 X15b X16-2 X17-2 Z1-2 Z3b
channel class LMS: LMS-a LMS-b
net class GMII_RX: GMII_RX_CLK GMII_RX_DV GMII_RX_ER GMII_RXD0 GMII_RXD1 GMII_RXD2 GMII_RXD3 GMII_RXD4 GMII_RXD5 GMII_RXD6 GMII_RXD7
net class GMII_TX: GMII_GTX_CLK GMII_TX_CLK GMII_TX_EN GMII_TX_ER GMII_TXD0 GMII_TXD1 GMII_TXD2 GMII_TXD3 GMII_TXD4 GMII_TXD5 GMII_TXD6 GMII_TXD7
net class RAM: RAM_A00 RAM_A01 RAM_A02 RAM_A03 RAM_A04 RAM_A05 RAM_A06 RAM_A07 RAM_A08 RAM_A09 RAM_A10 RAM_A11 RAM_A12 RAM_A13 RAM_A14 RAM_A15 RAM_A16 RAM_A17 RAM_A18 RAM_A19 RAM_A20 RAM_BWN0 RAM_BWN1 RAM_BWN2 RAM_BWN3 RAM_CENN RAM_CLK RAM_D00 RAM_D01 RAM_D02 RAM_D03 RAM_D04 RAM_D05 RAM_D06 RAM_D07 RAM_D08 RAM_D09 RAM_D10 RAM_D11 RAM_D12 RAM_D13 RAM_D14 RAM_D15 RAM_D16 RAM_D17 RAM_D18 RAM_D19 RAM_D20 RAM_D21 RAM_D22 RAM_D23 RAM_D24 RAM_D25 RAM_D26 RAM_D27 RAM_D28 RAM_D29 RAM_D30 RAM_D31 RAM_D32 RAM_D33 RAM_D34 RAM_D35 RAM_LDN RAM_OEN RAM_WEN
net class RX1: RX1_CLK/2 RX1D0 RX1D1 RX1D2 RX1D3 RX1D4 RX1D5 RX1D6 RX1D7 RX1D8 RX1D9 RX1D10 RX1D11 RX1EN RX1IQSEL
net class RX2: RX2_CLK/2 RX2D0 RX2D1 RX2D2 RX2D3 RX2D4 RX2D5 RX2D6 RX2D7 RX2D8 RX2D9 RX2D10 RX2D11 RX2EN RX2IQSEL
net class TX1: TX1CLK TX1D0 TX1D1 TX1D2 TX1D3 TX1D4 TX1D5 TX1D6 TX1D7 TX1D8 TX1D9 TX1D10 TX1D11 TX1EN TX1IQSEL
net class TX2: TX2CLK TX2D0 TX2D1 TX2D2 TX2D3 TX2D4 TX2D5 TX2D6 TX2D7 TX2D8 TX2D9 TX2D10 TX2D11 TX2EN TX2IQSEL
net class ResArray: NetR90_2 NetRA1_1 NetRA1_2 NetRA1_3 NetRA1_4 NetRA1_5 NetRA1_6 NetRA1_7 NetRA1_8 NetRA2_1 NetRA2_2 NetRA2_3 NetRA2_4 NetRA2_5 NetRA2_6 NetRA2_7 NetRA2_8 NetRA3_1 NetRA3_2 NetRA3_3 NetRA3_4 NetRA3_5 NetRA3_6 NetRA3_7 NetRA3_8
differential pair CLK_FPGA: +CLK_FPGA_P -CLK_FPGA_N
differential pair DIVSW1: +DIVSW1_P -DIVSW1_N
differential pair DIVSW2: +DIVSW2_P -DIVSW2_N

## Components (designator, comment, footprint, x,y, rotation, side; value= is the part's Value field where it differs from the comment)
C1 "2.2" C0402-Phillips 159.25,102.75 r270 top
C2 "0.1" C0402-Phillips 158.2,102.75 r270 top
C4 "0.1" C0402-Phillips 102.15,101.55 r180 top
C5 "0.1" C0402-Phillips 106.239,108.05 r270 top
C6 "100uF" cd7343 98.6,97 r0 top
C7 "0.1" C0402-Phillips 98.85,100.2 r180 top
C8 "0.1" C0402-Phillips 107.2,98.2 r270 top
C10 "0.1" C0402-Phillips 142.019,100.299 r270 top
C11 "2.2" C0402-Phillips 141.111,100.28 r270 top
C12 "10uF" CA3216 90.15,107.1 r180 top
C13 "0.1" C0402-Phillips 90.4,109.05 r180 top
C14 "0.1" C0402-Phillips 79.75,64.9 r90 top
C15 "0.1" C0402-Phillips 80.2,67.938 r270 top
C17 "100uF" cd7343 84.05,71.7 r180 top
C18 "0.1" C0402-Phillips 78.223,71.762 r180 top
C19 "220p" C0603-PHILLIPS 77.737,68.687 r180 top
C20 "0.1" C0402-Phillips 86.25,64.85 r270 top
C21 "0.1" C0402-Phillips 85.9,68.9 r0 top
C22 "0.1" C0402-Phillips 82.95,62.3 r270 top
C24 "0.1" C0402-Phillips 77.5,71 r0 top
C25 "0.1" C0402-Phillips 44.854,69.648 r0 top
C26 "0.1" C0402-Phillips 168.25,51.25 r90 bottom
C27 "0.1" C0402-Phillips 31.9,71.9 r180 top
C28 "0.1" C0402-Phillips 24.3,58 r90 bottom
C29 "0.1" C0402-Phillips 19.4,54.4 r180 bottom
C30 "0.1" C0402-Phillips 19.5,44.3 r180 bottom
C31 "0.1" C0402-Phillips 24.3,40.9 r270 bottom
C32 "1.0" C0603-PHILLIPS 25.65,40.8 r90 bottom
C33 "0.01" C0402-Phillips 20.3,58 r270 bottom
C34 "0.01" C0402-Phillips 19.4,51.4 r0 bottom
C35 "0.01" C0402-Phillips 19.4,47.3 r0 bottom
C36 "0.01" C0402-Phillips 20.3,40.7 r90 bottom
C37 "0.01" C0402-Phillips 35.9,59.45 r0 top
C38 "100uF" cd7343 41.75,62.2 r180 top
C39 "0.1" C0402-Phillips 45.25,59.1 r0 top
C40 "0.1" C0402-Phillips 39,59.1 r0 top
C41 "1.0" C0603-PHILLIPS 42.35,52.8 r90 bottom
C42 "0.1" C0402-Phillips 45.35,57.45 r0 top
C43 "0.1" C0402-Phillips 168.2,61.35 r90 bottom
C44-1 "0.1" C0402-Phillips 140.84,13.781 r0 top (schematic designator C44)
C44-2 "0.1" C0402-Phillips 140.5,63.55 r0 top (schematic designator C44)
C45-1 "100p" C0603-PHILLIPS 131.161,18.658 r90 top (schematic designator C45)
C45-2 "100p" C0603-PHILLIPS 131.2,67.95 r90 top (schematic designator C45)
C46-1 "0.1" C0402-Phillips 136.89,11.081 r90 top (schematic designator C46)
C46-2 "0.1" C0402-Phillips 136.45,60.85 r90 top (schematic designator C46)
C47-1 "0.1" C0402-Phillips 138.846,27.853 r180 top (schematic designator C47)
C47-2 "0.1" C0402-Phillips 138.65,77.1 r180 top (schematic designator C47)
C48-1 "0.1" C0402-Phillips 141.29,12.281 r0 top (schematic designator C48)
C48-2 "0.1" C0402-Phillips 140.74,61.526 r0 top (schematic designator C48)
C49-1 "0.1" C0402-Phillips 138.644,19.795 r180 top (schematic designator C49)
C49-2 "0.1" C0402-Phillips 138.444,69.494 r180 top (schematic designator C49)
C50-1 "0.1" C0402-Phillips 138.811,37.076 r180 top (schematic designator C50)
C50-2 "0.1" C0402-Phillips 138.7,86.1 r180 top (schematic designator C50)
C51-1 "100uF" cd7343 140.55,24.9 r0 top (schematic designator C51)
C51-2 "100uF" cd7343 140.65,74.3 r0 top (schematic designator C51)
C52-1 "100uF" cd7343 141,7.8 r0 top (schematic designator C52)
C52-2 "100uF" cd7343 140.95,57.45 r0 top (schematic designator C52)
C53-1 "100uF" cd7343 140.6,16.85 r0 top (schematic designator C53)
C53-2 "100uF" cd7343 140.7,66.35 r0 top (schematic designator C53)
C54-1 "100uF" cd7343 141.09,33.506 r0 top (schematic designator C54)
C54-2 "100uF" cd7343 141.1,82.7 r0 top (schematic designator C54)
C55-1 "0.1" C0402-Phillips 145.75,26.9 r90 top (schematic designator C55)
C55-2 "0.1" C0402-Phillips 145.8,76.25 r90 top (schematic designator C55)
C56-1 "0.1" C0402-Phillips 146.848,6.489 r0 top (schematic designator C56)
C56-2 "0.1" C0402-Phillips 146.998,55.794 r0 top (schematic designator C56)
C57-1 "0.1" C0402-Phillips 146.75,17.4 r90 top (schematic designator C57)
C57-2 "0.1" C0402-Phillips 146.9,66.7 r90 top (schematic designator C57)
C58-1 "0.1" C0402-Phillips 146.477,32.311 r270 top (schematic designator C58)
C58-2 "0.1" C0402-Phillips 146.25,81.35 r270 top (schematic designator C58)
C59-1 "0.1" C0402-Phillips 130.316,16.527 r180 top (schematic designator C59)
C59-2 "0.1" C0402-Phillips 130.355,65.819 r180 top (schematic designator C59)
C60-1 "0.1" C0402-Phillips 133.261,21.008 r270 top (schematic designator C60)
C60-2 "0.1" C0402-Phillips 133.3,70.3 r270 top (schematic designator C60)
C61-1 "0.1" C0402-Phillips 130.75,23.275 r180 top (schematic designator C61)
C61-2 "0.1" C0402-Phillips 130.8,72.6 r180 top (schematic designator C61)
C62-1 "0.1" C0402-Phillips 121.707,17.138 r270 bottom (schematic designator C62)
C62-2 "0.1" C0402-Phillips 121.746,66.43 r270 bottom (schematic designator C62)
C63-1 "0.1" C0402-Phillips 121.557,14.238 r90 top (schematic designator C63)
C63-2 "0.1" C0402-Phillips 121.596,63.53 r90 top (schematic designator C63)
C64-1 "10uF" CA3216 141.85,29.65 r180 top (schematic designator C64)
C64-2 "10uF" CA3216 141.7,79.1 r180 top (schematic designator C64)
C65-1 "10uF" CA3216 147.8,14.6 r180 top (schematic designator C65)
C65-2 "10uF" CA3216 147.7,64.2 r180 top (schematic designator C65)
C66-1 "10uF" CA3216 142.1,21.5 r180 top (schematic designator C66)
C66-2 "10uF" CA3216 141.7,71 r180 top (schematic designator C66)
C67-1 "10uF" CA3216 143.5,38.25 r90 top (schematic designator C67)
C67-2 "10uF" CA3216 143.7,87.3 r90 top (schematic designator C67)
C68-1 "1.0" C0603-PHILLIPS 120.107,11.188 r0 top (schematic designator C68)
C68-2 "1.0" C0603-PHILLIPS 120.146,60.48 r0 top (schematic designator C68)
C69-1 "0.1" C0402-Phillips 144.85,28.95 r90 top (schematic designator C69)
C69-2 "0.1" C0402-Phillips 145.5,77.7 r180 top (schematic designator C69)
C70-1 "0.1" C0402-Phillips 145.39,10.831 r90 top (schematic designator C70)
C70-2 "0.1" C0402-Phillips 145.2,60.4 r90 top (schematic designator C70)
C71-1 "0.1" C0402-Phillips 145.39,19.577 r90 top (schematic designator C71)
C71-2 "0.1" C0402-Phillips 145.09,70.176 r90 top (schematic designator C71)
C72-1 "0.1" C0402-Phillips 145.351,37.119 r90 top (schematic designator C72)
C72-2 "0.1" C0402-Phillips 145.2,86.15 r90 top (schematic designator C72)
C73-1 "10.0" C0603-Phillips 130.307,15.388 r0 bottom (schematic designator C73)
C73-2 "10.0" C0603-Phillips 130.346,64.68 r0 bottom (schematic designator C73)
C74-1 "1.0" C0603-PHILLIPS 122.757,13.888 r270 bottom (schematic designator C74)
C74-2 "1.0" C0603-PHILLIPS 122.796,63.18 r270 bottom (schematic designator C74)
C75-1 "10.0" C0603-Phillips 128.311,26.308 r90 bottom (schematic designator C75)
C75-2 "10.0" C0603-Phillips 128.325,75.6 r90 bottom (schematic designator C75)
C76-1 "1.0" C0603-PHILLIPS 116.562,23.155 r90 top (schematic designator C76)
C76-2 "1.0" C0603-PHILLIPS 116.601,72.447 r90 top (schematic designator C76)
C77-1 "1.0" C0603-PHILLIPS 120.657,13.838 r270 top (schematic designator C77)
C77-2 "1.0" C0603-PHILLIPS 120.696,63.13 r270 top (schematic designator C77)
C78-1 "0.1" C0402-Phillips 127.207,16.588 r180 bottom (schematic designator C78)
C78-2 "0.1" C0402-Phillips 127.246,65.88 r180 bottom (schematic designator C78)
C79-1 "0.1" C0402-Cirq 126.157,23.188 r180 bottom (schematic designator C79)
C79-2 "0.1" C0402-Cirq 126.196,72.48 r180 bottom (schematic designator C79)
C80-1 "0.1" C0402-Cirq 126.707,20.438 r270 bottom (schematic designator C80)
C80-2 "0.1" C0402-Cirq 126.746,69.73 r270 bottom (schematic designator C80)
C81-1 "1.0" C0603-PHILLIPS 120.961,26.308 r90 bottom (schematic designator C81)
C81-2 "1.0" C0603-PHILLIPS 121,75.6 r90 bottom (schematic designator C81)
C82-1 "470p" C0603-PHILLIPS 131.157,18.438 r0 bottom (schematic designator C82)
C82-2 "470p" C0603-PHILLIPS 131.196,67.73 r0 bottom (schematic designator C82)
C83-1 "8n2" C0603-PHILLIPS 131.107,11.738 r180 top (schematic designator C83)
C83-2 "8n2" C0603-PHILLIPS 131.146,61.03 r180 top (schematic designator C83)
C84-1 "150p" C0603-PHILLIPS 131.107,14.288 r180 top (schematic designator C84)
C84-2 "150p" C0603-PHILLIPS 131.146,63.58 r180 top (schematic designator C84)
C85-1 "0.1" C0402-Phillips 122.007,11.238 r90 top (schematic designator C85)
C85-2 "0.1" C0402-Phillips 122.046,60.53 r90 top (schematic designator C85)
C86-1 "0.1" C0402-Phillips 121.05,26.675 r90 top (schematic designator C86)
C86-2 "0.1" C0402-Phillips 121.025,76 r90 top (schematic designator C86)
C87-1 "0.1" C0402-Phillips 127.557,14.388 r270 top (schematic designator C87)
C87-2 "0.1" C0402-Phillips 127.596,63.68 r270 top (schematic designator C87)
C88-1 "0.1" C0402-Cirq 122.857,23.088 r0 bottom (schematic designator C88)
C88-2 "0.1" C0402-Cirq 122.896,72.38 r0 bottom (schematic designator C88)
C89-1 "0.1" C0402-Cirq 126.707,18.138 r90 bottom (schematic designator C89)
C89-2 "0.1" C0402-Cirq 126.746,67.43 r90 bottom (schematic designator C89)
C90-1 "0.1" C0402-Phillips 127.1,26.35 r90 top (schematic designator C90)
C90-2 "0.1" C0402-Phillips 127.15,75.65 r90 top (schematic designator C90)
C91-1 "0.1" C0402-Phillips 130.761,22.508 r0 top (schematic designator C91)
C91-2 "0.1" C0402-Phillips 130.8,71.8 r0 top (schematic designator C91)
C92-1 "0.1" C0402-Cirq 125.057,17.688 r0 bottom (schematic designator C92)
C92-2 "0.1" C0402-Cirq 125.096,66.98 r0 bottom (schematic designator C92)
C93-1 "0.1" C0402-Phillips 130.75,26.35 r0 top (schematic designator C93)
C93-2 "0.1" C0402-Phillips 130.8,75.65 r0 top (schematic designator C93)
C94-1 "0.1" C0402-Phillips 122.857,11.238 r90 top (schematic designator C94)
C94-2 "0.1" C0402-Phillips 122.896,60.53 r90 top (schematic designator C94)
C95-1 "100p" C0603-PHILLIPS 126.507,11.288 r270 top (schematic designator C95)
C95-2 "100p" C0603-PHILLIPS 126.546,60.58 r270 top (schematic designator C95)
C96-1 "?" C0603-PHILLIPS 124.657,14.688 r180 top (schematic designator C96)
C96-2 "?" C0603-PHILLIPS 124.696,63.98 r180 top (schematic designator C96)
C97-1 "150p" C0603-PHILLIPS 131.161,25.408 r180 top (schematic designator C97)
C97-2 "150p" C0603-PHILLIPS 131.25,74.65 r180 top (schematic designator C97)
C98-1 "470p" C0603-PHILLIPS 131.161,24.408 r0 bottom (schematic designator C98)
C98-2 "470p" C0603-PHILLIPS 131.2,73.7 r0 bottom (schematic designator C98)
C99-1 "8n2" C0603-PHILLIPS 131.25,25.575 r0 bottom (schematic designator C99)
C99-2 "8n2" C0603-PHILLIPS 131.3,74.875 r0 bottom (schematic designator C99)
C100-1 "1.0" C0603-PHILLIPS 117.146,39.294 r90 top (schematic designator C100)
C100-2 "1.0" C0603-PHILLIPS 117.185,88.586 r90 top (schematic designator C100)
C101-1 "1.0" C0603-PHILLIPS 118.511,39.258 r90 top (schematic designator C101)
C101-2 "1.0" C0603-PHILLIPS 118.55,88.55 r90 top (schematic designator C101)
C102-1 "100p" C0603-PHILLIPS 123.011,27.108 r90 top (schematic designator C102)
C102-2 "100p" C0603-PHILLIPS 123.05,76.4 r90 top (schematic designator C102)
C103-1 "100p" C0603-PHILLIPS 121.961,27.108 r90 top (schematic designator C103)
C103-2 "100p" C0603-PHILLIPS 122,76.4 r90 top (schematic designator C103)
C104-1 "100p" C0603-PHILLIPS 123.857,12.388 r270 top (schematic designator C104)
C104-2 "100p" C0603-PHILLIPS 123.896,61.68 r270 top (schematic designator C104)
C105-1 "100p" C0603-PHILLIPS 125.357,12.388 r270 top (schematic designator C105)
C105-2 "100p" C0603-PHILLIPS 125.396,61.68 r270 top (schematic designator C105)
C106-1 "100p" C0603-PHILLIPS 126.157,27.088 r90 top (schematic designator C106)
C106-2 "100p" C0603-PHILLIPS 126.196,76.38 r90 top (schematic designator C106)
C107-1 "100p" C0603-PHILLIPS 125.111,27.108 r90 top (schematic designator C107)
C107-2 "100p" C0603-PHILLIPS 125.15,76.4 r90 top (schematic designator C107)
C108-1 "1.0" C0603-PHILLIPS 122.711,39.208 r90 top (schematic designator C108)
C108-2 "1.0" C0603-PHILLIPS 122.75,88.5 r90 top (schematic designator C108)
C109-1 "1.0" C0603-PHILLIPS 123.961,39.208 r90 top (schematic designator C109)
C109-2 "1.0" C0603-PHILLIPS 124,88.5 r90 top (schematic designator C109)
C110-1 "100p" C0603-PHILLIPS 119.507,6.788 r180 top (schematic designator C110)
C110-2 "100p" C0603-PHILLIPS 119.546,56.08 r180 top (schematic designator C110)
C111-1 "100p" C0603-PHILLIPS 133.661,30.608 r270 top (schematic designator C111)
C111-2 "100p" C0603-PHILLIPS 133.45,82 r270 top (schematic designator C111)
C112-1 "100p" C0603-PHILLIPS 133.661,36.108 r270 top (schematic designator C112)
C112-2 "100p" C0603-PHILLIPS 133.45,83.5 r270 top (schematic designator C112)
C113 "0.1" C0402-Phillips 79.946,80.746 r270 top
C114 "470uF" CASE-G 49.25,103.15 r90 top
C115 "470uF" CASE-G 8.8,101.4 r90 top
C116 "470uF" CASE-G 28.95,101.6 r90 top
C117 "470uF" CASE-G 68.9,103.2 r90 top
C118 "4,7uF" c1206 56.215,108.118 r90 top
C119 "4,7uF" c1206 16.75,108.4 r90 top
C120 "4,7uF" c1206 37.8,108.3 r90 top
C121 "4,7uF" c1206 78.7,108.65 r90 top
C122 "4,7uF" c1206 58.965,108.068 r90 top
C123 "4,7uF" c1206 14.45,108.4 r90 top
C124 "4,7uF" c1206 35.35,108.3 r90 top
C125 "100uF" cd7343 98.5,75.2 r0 top
C126 "4,7uF" c1206 76.3,108.65 r90 top
C127 "0.1" C0402-Phillips 100.4,80.6 r180 top
C128 "220p" C0603-PHILLIPS 61.315,96.118 r180 top
C129 "220p" C0603-PHILLIPS 19.95,96.15 r180 top
C130 "220p" C0603-PHILLIPS 41.25,96.3 r180 top
C131 "470uF" CASE-G 68.7,81.15 r0 top
C132 "22n" C0603-PHILLIPS 63.5,95.35 r270 top
C133 "22n" C0603-PHILLIPS 22.25,95.5 r270 top
C134 "22n" C0603-PHILLIPS 43.3,95.5 r270 top
C135 "0.01" C0402-Phillips 99.7,87 r90 top
C136 "4,7uF" c1206 58.35,80.05 r270 top
C137 "4,7uF" c1206 19.45,81.1 r270 top
C138 "4,7uF" c1206 37.9,80.15 r270 top
C139 "0.1" C0402-Phillips 108.15,91.5 r90 top
C140 "470uF" CASE-G 8.3,81.75 r0 top
C141 "470uF" CASE-G 49.45,81.25 r0 top
C142 "470uF" CASE-G 29.65,81.4 r0 top
C143 "0.1" C0402-Phillips 58.5,70.1 r90 top
C144 "0.1" C0402-Phillips 26,65.4 r270 top
C145 "0.1" C0402-Phillips 48.5,8.95 r180 top
C146 "100uF" cd7343 108.4,75.25 r180 top
C147 "0.1" C0402-Phillips 71.95,70.1 r90 top
C148 "0.1" C0402-Phillips 41.2,81.3 r270 top
C149 "2.2" C0402-Phillips 108.25,40 r270 top
C150 "220p" C0603-PHILLIPS 70.55,70.4 r90 top
C151 "220p" C0603-PHILLIPS 57.4,70.45 r90 top
C152 "220p" C0603-PHILLIPS 24.6,65.2 r270 top
C153 "220p" C0603-PHILLIPS 48.25,7.8 r180 top
C154 "220p" C0603-PHILLIPS 39.9,81 r270 top
C155 "2.2" C0402-Phillips 108.25,38.05 r270 top
C156 "0.1" C0402-Phillips 58.05,64.85 r180 top
C157 "0.1" C0402-Phillips 20.2,64.15 r90 top
C158 "0.1" C0402-Phillips 50.4,3.05 r270 top
C159 "0.1" C0402-Phillips 71.35,63.45 r0 top
C160 "0.01" C0402-Phillips 108.25,35.4 r90 top
C161 "220p" C0603-PHILLIPS 71.7,64.85 r0 top
C162 "220p" C0603-PHILLIPS 57.85,63.55 r180 top
C163 "220p" C0603-PHILLIPS 21.3,64.5 r90 top
C164 "220p" C0603-PHILLIPS 51.4,2.85 r270 top
C165 "100uF" cd7343 67.55,67.2 r270 top
C166 "100uF" cd7343 61.45,67.2 r270 top
C167 "100uF" cd7343 19.35,60.35 r0 top
C168 "100uF" cd7343 44.9,4.55 r0 top
C169 "10uF" CA3216 106.25,35.1 r90 top
C170 "1.0" C0603-PHILLIPS 106,42 r0 top
C171 "100uF" cd7343 11.7,37.6 r0 top
C172 "0.1" C0402-cirq 60.5,46 r0 bottom
C174 "0.1" C0402-cirq 60.5,49 r0 bottom
C175 "0.1" C0402-cirq 71.5,47 r180 bottom
C176 "0.1" C0402-cirq 59,38.5 r270 bottom
C177 "0.1" C0402-cirq 60,50.5 r90 bottom
C178 "0.1" C0402-cirq 72,52.5 r270 bottom
C179 "0.1" C0402-cirq 74.95,45.45 r90 bottom
C180 "0.1" C0402-cirq 75,41.5 r90 bottom
C181 "0.1" C0402-cirq 73,40.5 r90 bottom
C182 "0.1" C0402-cirq 67,41.5 r90 bottom
C183 "0.1" C0402-cirq 64.5,40 r180 bottom
C184 "0.1" C0402-cirq 60,41.5 r270 bottom
C185 "0.1" C0402-cirq 55.95,39.55 r270 bottom
C186 "0.1" C0402-cirq 56,54.5 r270 bottom
C187 "0.1" C0402-cirq 61.5,38 r0 bottom
C188 "0.1" C0402-cirq 64.5,38 r0 bottom
C189 "0.1" C0402-cirq 68.5,38 r0 bottom
C190 "0.1" C0402-cirq 71.5,38 r0 bottom
C191 "0.1" C0402-cirq 76,36.5 r90 bottom
C192 "0.1" C0402-cirq 74,48.5 r90 bottom
C193 "0.1" C0402-cirq 72,40.5 r90 bottom
C194 "0.1" C0402-cirq 60.5,40 r0 bottom
C196 "0.1" C0402-cirq 67,43.5 r270 bottom
C197 "0.1" C0402-cirq 62.5,45 r180 bottom
C198 "0.1" C0402-cirq 70.5,53 r0 bottom
C199 "0.1" C0402-cirq 61,52.5 r270 bottom
C200 "0.1" C0402-cirq 68.5,46 r0 bottom
C201 "0.1" C0402-cirq 63.5,55 r180 bottom
C202 "0.1" C0402-cirq 70.5,55 r180 bottom
C203 "0.1" C0402-cirq 66.5,52 r180 bottom
C204 "0.1" C0402-cirq 68.5,41 r180 bottom
C205 "0.1" C0402-cirq 73.5,45 r180 bottom
C206 "0.1" C0402-cirq 64,42.5 r270 bottom
C207 "0.1" C0402-cirq 74,52.5 r90 bottom
C208 "0.1" C0402-cirq 57.45,41 r0 bottom
C209 "0.1" C0402-cirq 55.95,41.5 r90 bottom
C210 "0.1" C0402-cirq 59,45.5 r270 bottom
C211 "0.1" C0402-cirq 57,50.5 r270 bottom
C212 "0.1" C0402-cirq 56,45.5 r90 bottom
C213 "0.1" C0402-cirq 59.5,48 r180 bottom
C214 "2.2" C0402-Phillips 15.8,34.5 r0 top
C215 "0.1" C0402-Phillips 67.7,2.7 r180 bottom
C216 "0.1" C0402-Phillips 64.25,2.7 r0 bottom
C217 "0.1" C0402-Phillips 70.7,2.7 r180 bottom
C218 "0.1" C0402-Phillips 60.3,2.7 r180 bottom
C219 "0.1" C0402-Phillips 57.45,10.9 r270 bottom
C220 "0.1" C0402-Phillips 60.3,17.95 r180 bottom
C221 "0.1" C0402-Phillips 64.2,17.95 r0 bottom
C222 "0.1" C0402-Phillips 67.05,17.95 r0 bottom
C223 "0.1" C0402-Phillips 74.6,3.35 r270 bottom
C224 "0.1" C0402-Phillips 70.65,17.95 r180 bottom
C225 "0.1" C0402-Phillips 74.6,17.95 r0 bottom
C226 "0.1" C0402-Phillips 77.55,15.5 r270 bottom
C227 "0.1" C0402-Phillips 77.55,10.85 r90 bottom
C228 "2.2" C0402-Phillips 34,42 r0 top
C229 "0.1" C0402-Phillips 35.3,46.5 r90 bottom
C230 "0.1" C0402-Phillips 41.3,52.5 r270 bottom
C231 "0.1" C0402-Phillips 41.5,48.3 r180 bottom
C232 "0.1" C0402-Phillips 38.1,46.5 r90 bottom
C233 "0.1" C0402-Phillips 40.5,46.5 r90 bottom
C234 "0.1" C0402-Phillips 41.5,50.3 r180 bottom
C235 "0.1" C0402-Phillips 43.1,46.3 r90 bottom
C236 "0.1" C0402-Phillips 40.5,52.5 r270 bottom
C237 "0.1" C0402-Phillips 36.4,53.65 r0 bottom
C238 "0.1" C0402-Phillips 36.5,46.5 r90 bottom
C239 "0.1" C0402-Phillips 39.6,46.5 r90 bottom
C240 "0.1" C0402-Phillips 34.9,56.8 r90 top
C241 "0.1" C0402-Phillips 35.5,51.5 r0 bottom
C242 "0.1" C0402-Phillips 33.4,50.8 r0 bottom
C243 "0.1" C0402-Phillips 35.5,49.05 r0 bottom
C244 "0.1" C0402-Phillips 35.5,47.9 r0 bottom
C245 "0.1" C0402-Phillips 33.3,47.3 r0 bottom
C246 "2.2" C0402-cirq 65,41.5 r270 bottom
C247 "2.2" C0402-cirq 66.5,53 r0 bottom
C248 "2.2" C0402-cirq 62,43.5 r90 bottom
C249 "2.2" C0402-cirq 61,47.5 r90 bottom
C250 "2.2" C0402-cirq 61,44.5 r90 bottom
C251 "2.2" C0402-cirq 59.5,55 r0 bottom
C252 "2.2" C0402-cirq 67.5,55 r0 bottom
C254 "2.2" C0402-cirq 72.5,55 r180 bottom
C255 "2.2" C0402-cirq 68.5,48 r180 bottom
C256 "2.2" C0402-cirq 68.5,53 r0 bottom
C257 "2.2" C0402-cirq 63.5,50 r180 bottom
C258 "2.2" C0402-cirq 67.5,50 r0 bottom
C259 "2.2" C0402-cirq 70.5,50 r0 bottom
C260 "2.2" C0402-cirq 68.5,45 r180 bottom
C261 "4,7uF" c1206 77.95,79.8 r270 top
C262 "2.2" C0402-cirq 64.5,44 r0 bottom
C263 "2.2" C0402-cirq 63.5,47 r0 bottom
C264 "2.2" C0402-cirq 65.5,46 r0 bottom
C265 "2.2" C0402-cirq 63.5,49 r0 bottom
C266 "220p" C0603-PHILLIPS 80,96.4 r180 top
C267 "22n" C0603-PHILLIPS 82,95.65 r270 top
C268 "2.2" C0402-cirq 66.5,48 r180 bottom
C269 "220p" C0603-PHILLIPS 95.5,78.6 r180 top
C270 "0.1" C0402-cirq 65.5,47 r180 bottom
C271 "0.1" C0402-cirq 67.5,49 r180 bottom
C272 "0.1" C0402-cirq 66.5,45 r180 bottom
C273 "0.1" C0402-cirq 63.5,46 r0 bottom
C274 "0.1" C0402-cirq 64.5,45 r0 bottom
C275 "0.1" C0402-Phillips 137.25,102.5 r90 top
C276 "0.1" C0402-cirq 67.5,47 r180 bottom
C277 "0.1" C0402-cirq 64.5,48 r0 bottom
C278 "0.1" C0402-Phillips 92.85,100.75 r180 top
C279 "2.2" C0402-Phillips 99.35,67.4 r90 top
C280 "0.1" C0402-Phillips 41.35,46.5 r90 bottom
C281 "0.1" C0402-Phillips 33.9,53.1 r270 bottom
C282 "0.1" C0402-Phillips 35.5,49.95 r0 bottom
C283 "33uF CER" C0805-Phillips 30.7,57.6 r90 top
C284 "33uF CER" C0805-Phillips 41.65,57.75 r90 top
C285 "33uF CER" C0805-Phillips 30.8,45.1 r270 top
C286 "2.2" C0402-Phillips 40.4,56.85 r270 top
C287 "2.2" C0402-Phillips 32.25,45.6 r90 top
C288 "0.1" C0402-Phillips 120.2,47.8 r180 top
C289 "0.1" C0402-Phillips 115.55,48.35 r90 top
C292 "0.1" C0402-Phillips 123.551,43.256 r180 top
C293 "0.1" C0402-Phillips 124.85,47.85 r0 top
C294 "0.1" C0402-Phillips 120.151,43.256 r180 top
C295 "0.1" C0402-Phillips 118.7,48.625 r180 top
C296 "0.1" C0402-Phillips 150.901,46.756 r90 top
C297 "0.1" C0402-Phillips 150.851,52.206 r90 top
C298 "2.2" C0402-Phillips 148.5,47.15 r90 top
C299 "2.2" C0402-Phillips 148.551,52.756 r90 top
C300 "100p" C0603-PHILLIPS 147.451,43.556 r90 top
C301 "100p" C0603-PHILLIPS 147.451,49.456 r90 top
C302 "33p" C0603-PHILLIPS 144.051,45.856 r180 top
C303 "33p" C0603-PHILLIPS 143.951,51.806 r180 top
C304 "100p" C0603-PHILLIPS 144.051,47.306 r180 top
C305 "100p" C0603-PHILLIPS 143.901,53.256 r180 top
C306 "2.2" C0402-Phillips 151.4,42.4 r0 top
C307 "100p" C0603-PHILLIPS 153.75,45.15 r0 top
C308 "2.2" C0402-Phillips 151.851,46.756 r90 top
C309 "100p" C0603-PHILLIPS 153.85,50.4 r0 top
C310 "100p" C0603-PHILLIPS 153.8,42.5 r0 top
C311 "100p" C0603-PHILLIPS 153.8,47.25 r0 top
C312 "0.1" C0402-Phillips 132.903,97.14 r0 top
C313 "0.1" C0402-Phillips 136.5,97.2 r180 top
C314 "0.1" C0402-Phillips 139.2,97.25 r0 top
C315 "0.1" C0402-Phillips 141.5,97.25 r0 top
C316 "0.01" C0603-PHILLIPS 9.85,13.8 r270 top
C317 "10X20v" CB3528 13,16.7 r0 top
C318 "0.1" C0603-PHILLIPS 19.2,4.25 r180 top
C319 "0.1" C0603-PHILLIPS 15.75,4.25 r0 top
D1 "STPS3L40S" SMC 47.45,90.25 r0 top
D2 "STPS3L40S" SMC 6.5,90.95 r0 top
D3 "STPS3L40S" SMC 27.35,90.8 r0 top
D4 "STPS3L40S" SMC 67.45,90.15 r0 top
D5 "STPS3L40S" SMC 6.55,63.1 r0 top
J1 "PLS-2" PLT-2 34.9,70.7 r270 top
L1 "TI160808U601" TI160808-PHILLIPS 101.85,100.2 r180 top
L2 "TI160808U601" TI160808-PHILLIPS 140.05,99.85 r270 top
L3 "TI160808U601" TI160808-PHILLIPS 77.763,70.043 r180 top
L4 "TI160808U601" TI160808-PHILLIPS 27,40.8 r90 bottom
L5 "TI160808U601" TI160808-PHILLIPS 43.35,58.25 r270 top
L6-1 "TI160808U601" TI160808-PHILLIPS 133.461,18.658 r90 top (schematic designator L6)
L6-2 "TI160808U601" Ti160808-Phillips 133.5,67.95 r90 top (schematic designator L6)
L7-1 "TI160808U601" TI160808-PHILLIPS 141.14,27.863 r0 top (schematic designator L7)
L7-2 "TI160808U601" Ti160808-Phillips 140.85,77.1 r0 top (schematic designator L7)
L8-1 "TI160808U601" TI160808-PHILLIPS 141.54,11.231 r0 top (schematic designator L8)
L8-2 "TI160808U601" Ti160808-Phillips 140.99,60.476 r0 top (schematic designator L8)
L9-1 "TI160808U601" TI160808-PHILLIPS 141.134,19.816 r0 top (schematic designator L9)
L9-2 "TI160808U601" Ti160808-Phillips 140.934,69.516 r0 top (schematic designator L9)
L10-1 "TI160808U601" TI160808-PHILLIPS 141.09,37.006 r0 top (schematic designator L10)
L10-2 "TI160808U601" Ti160808-Phillips 140.95,86.05 r0 top (schematic designator L10)
L11-1 "TI160808U601" Ti160808-Phillips 121.657,13.888 r270 bottom (schematic designator L11)
L11-2 "TI160808U601" Ti160808-Phillips 121.696,63.18 r270 bottom (schematic designator L11)
L12-1 "TI160808U601" Ti160808-Phillips 123.811,13.908 r90 bottom (schematic designator L12)
L12-2 "TI160808U601" Ti160808-Phillips 123.85,63.2 r90 bottom (schematic designator L12)
L13-1 "TI160808U601" Ti160808-Phillips 131.157,20.988 r180 bottom (schematic designator L13)
L13-2 "TI160808U601" Ti160808-Phillips 131.196,70.28 r180 bottom (schematic designator L13)
L14-1 "TI160808U601" Ti160808-Phillips 130.357,14.088 r180 bottom (schematic designator L14)
L14-2 "TI160808U601" Ti160808-Phillips 130.396,63.38 r180 bottom (schematic designator L14)
L15-1 "TI160808U601" Ti160808-Phillips 129.411,26.308 r270 bottom (schematic designator L15)
L15-2 "TI160808U601" Ti160808-Phillips 129.4,75.6 r270 bottom (schematic designator L15)
L16-1 "TI160808U601" Ti160808-Phillips 131.15,24.225 r0 top (schematic designator L16)
L16-2 "TI160808U601" Ti160808-Phillips 131.2,73.55 r0 top (schematic designator L16)
L17-1 "TI160808U601" Ti160808-Phillips 117.311,22.408 r0 bottom (schematic designator L17)
L17-2 "TI160808U601" Ti160808-Phillips 117.35,71.7 r0 bottom (schematic designator L17)
L18-1 "TI160808U601" Ti160808-Phillips 133.161,20.458 r90 bottom (schematic designator L18)
L18-2 "TI160808U601" Ti160808-Phillips 133.2,69.75 r90 bottom (schematic designator L18)
L19-1 "TI160808U601" Ti160808-Phillips 131.161,15.408 r0 top (schematic designator L19)
L19-2 "TI160808U601" Ti160808-Phillips 131.2,64.7 r0 top (schematic designator L19)
L20-1 "TI160808U601" Ti160808-Phillips 120.557,13.888 r270 bottom (schematic designator L20)
L20-2 "TI160808U601" Ti160808-Phillips 120.596,63.18 r270 bottom (schematic designator L20)
L21-1 "TI160808U601" Ti160808-Phillips 120.125,27.05 r90 top (schematic designator L21)
L21-2 "TI160808U601" Ti160808-Phillips 120.05,76.35 r90 top (schematic designator L21)
L22-1 "TI160808U601" Ti160808-Phillips 128.607,13.988 r90 top (schematic designator L22)
L22-2 "TI160808U601" Ti160808-Phillips 128.646,63.28 r90 top (schematic designator L22)
L23-1 "TI160808U601" Ti160808-Phillips 122.207,27.088 r90 bottom (schematic designator L23)
L23-2 "TI160808U601" Ti160808-Phillips 122.246,76.38 r90 bottom (schematic designator L23)
L24-1 "TI160808U601" Ti160808-Phillips 131.107,16.888 r180 bottom (schematic designator L24)
L24-2 "TI160808U601" Ti160808-Phillips 131.146,66.18 r180 bottom (schematic designator L24)
L25-1 "TI160808U601" Ti160808-Phillips 128.075,26.725 r90 top (schematic designator L25)
L25-2 "TI160808U601" Ti160808-Phillips 128.05,76.05 r90 top (schematic designator L25)
L26-1 "TI160808U601" Ti160808-Phillips 131.161,21.608 r180 top (schematic designator L26)
L26-2 "TI160808U601" Ti160808-Phillips 131.2,70.9 r180 top (schematic designator L26)
L27-1 "TI160808U601" Ti160808-Phillips 124.911,13.908 r270 bottom (schematic designator L27)
L27-2 "TI160808U601" Ti160808-Phillips 124.95,63.2 r270 bottom (schematic designator L27)
L28-1 "TI160808U601" Ti160808-Phillips 131.15,27.325 r180 top (schematic designator L28)
L28-2 "TI160808U601" Ti160808-Phillips 131.2,76.65 r180 top (schematic designator L28)
L29-1 "TI160808U601" Ti160808-Phillips 127.737,11.292 r270 top (schematic designator L29)
L29-2 "TI160808U601" Ti160808-Phillips 127.776,60.584 r270 top (schematic designator L29)
L30-1 "39nH" TF160808-Phillips 122.757,13.888 r90 top (schematic designator L30)
L30-2 "39nH" TF160808-Phillips 122.796,63.18 r90 top (schematic designator L30)
L31-1 "39nH" TF160808-Phillips 126.507,13.938 r90 top (schematic designator L31)
L31-2 "39nH" TF160808-Phillips 126.546,63.23 r90 top (schematic designator L31)
L32-1 "4,7nH" TF160808-Phillips 126.961,33.508 r90 top (schematic designator L32)
L32-2 "4,7nH" TF160808-Phillips 127,82.8 r90 top (schematic designator L32)
L33-1 "4,7nH" TF160808-Phillips 126.961,36.208 r90 top (schematic designator L33)
L33-2 "4,7nH" TF160808-Phillips 127,85.5 r90 top (schematic designator L33)
L34 "TI201209-121" TI2012-Phillips 99.8,78.6 r0 top
L35 "15 uH" DS3316 77,89.1 r90 top
L36 "15 uH" DS3316 57.25,89.4 r90 top
L37 "15 uH" DS3316 16.75,88.85 r90 top
L38 "15 uH" DS3316 37.55,89.45 r90 top
L39 "4.7uH" CR1812 110.6,41.7 r270 top
L40 "TI201209-121" TI2012-Phillips 70.75,67.35 r270 top
L41 "TI201209-121" TI2012-Phillips 58.3,67.3 r270 top
L42 "TI201209-121" TI2012-Phillips 22.9,64.8 r270 top
L43 "TI201209-121" TI2012-Phillips 50.5,6.65 r270 top
L44 "4.7uH" CR1812 110.6,34.9 r270 top
L45 "TI160808U601" Ti160808-Phillips 32.2,57.2 r270 top
L46 "TI160808U601" TI160808-PHILLIPS 33.85,57.2 r270 top
L47 "TI160808U601" Ti160808-Phillips 122.5,47.8 r0 top
L48 "TI160808U601" Ti160808-Phillips 117.45,47.35 r0 top
L49 "TI160808U601" Ti160808-Phillips 149.751,47.006 r90 top
L50 "TI160808U601" Ti160808-Phillips 149.65,52.45 r90 top
L51 "39nH" TF160808-Phillips 146.701,45.856 r0 top
L52 "39nH" TF160808-Phillips 146.701,51.806 r0 top
L53 "39nH" TF160808-Phillips 151.85,44.4 r90 top
L54 "39nH" TF160808-Phillips 151.85,49.55 r90 top
L55 "TI160808U601" Ti160808-Phillips 11.4,13.8 r90 top
LED1 "L7104SA/3GD" L-7104SA/3 172,7.5 r270 top
LED2 "L7104SA/3GD" L-7104SA/3 172,22.5 r270 top
LED3 "L7104SA/3GD" L-7104SA/3 172,105.15 r270 top
LED4 "LED0603" LED-0603y 74.8,67.7 r180 top
LED5 "Tx/Rx" LED-0603y 31.15,42.6 r180 top
LED6 "SPEED" LED-0603y 31.1,40.3 r180 top
Q1 "FDV301N" SOT23-Philips 166.5,12.3 r270 top
Q2 "FDV301N" SOT23-Philips 74.65,63.55 r180 top
Q3 "BCP69" SOT-223 21.5,36 r90 top
Q4 "BC817-40" SOT23-Philips 89,75.8 r90 top
R1 "330" R0603-PHILLIPS 163.3,110.45 r0 top
R2 "??" R0603-PHILLIPS 102.25,103 r0 top
R3 "0" R0603-PHILLIPS 103,103.75 r270 top
R4 "1k" R0603-PHILLIPS 106.189,105.5 r90 top
R5 "100" R0603-PHILLIPS 92.8,102.05 r0 top
R6 "2k2" R0603-PHILLIPS 130.85,101.05 r0 top
R7 "0" R0603-PHILLIPS 131.6,101.8 r270 top
R8 "220" R0603-PHILLIPS 95.7,100.1 r0 top
R9 "750" R0603-PHILLIPS 140.836,103.503 r0 top
R10 "750" R0603-PHILLIPS 140.843,102.077 r180 top
R11 "1k" R0603-PHILLIPS 77.7,67.4 r180 top
R12 "3k3" R0603-PHILLIPS 130.85,99.3 r0 top
R13 "330" R0603-PHILLIPS 163.4,108.9 r180 top
R14 "10" R0603-PHILLIPS 34.604,39.383 r90 bottom
R15 "10" R0603-PHILLIPS 37.341,39.37 r90 bottom
R16 "10" R0603-PHILLIPS 38.7,39.35 r90 bottom
R17 "10" R0603-PHILLIPS 40.55,39.35 r90 bottom
R18 "10k" R0603-PHILLIPS 33.388,39.421 r90 bottom
R19 "10k" R0603-PHILLIPS 42.1,39.35 r90 bottom
R20 "10k" R0603-PHILLIPS 36.036,39.37 r270 bottom
R21 "10k" R0603-PHILLIPS 59.275,52.375 r180 bottom
R22 "4k7" R0603-PHILLIPS 79.4,56.2 r180 top
R23 "4k7" R0603-PHILLIPS 62,48.95 r270 bottom
R24 "4k7" R0603-PHILLIPS 65.566,50.146 r90 bottom
R25 "2k" R0603-PHILLIPS 35,67.15 r180 top
R26 "1k" R0603-PHILLIPS 31.34,69.396 r270 top
R27 "1k" R0603-PHILLIPS 32.7,69.4 r270 top
R28 "330" R0603-PHILLIPS 164.95,15.45 r270 top
R29 "1k" R0603-PHILLIPS 72.55,66.95 r90 top
R30 "4k7" R0603-PHILLIPS 74.85,66.15 r0 top
R31 "4k7" R0603-PHILLIPS 53.5,56.8 r90 bottom
R32 "4k7" R0603-PHILLIPS 63.4,53.2 r0 bottom
R33 "1k" R0603-PHILLIPS 166.05,3.15 r90 top
R34 "1k" R0603-PHILLIPS 164.25,3.2 r90 top
R35 "1k" R0603-PHILLIPS 162.55,3.2 r90 top
R36 "1k" R0603-PHILLIPS 167.45,18.3 r90 top
R37 "1k" R0603-PHILLIPS 164.95,18.35 r90 top
R38 "1k" R0603-PHILLIPS 162.45,18.45 r90 top
R39 "0" R0603-PHILLIPS 6,40.1 r180 bottom
R40 "0" R0603-PHILLIPS 5.7,58.4 r180 bottom
R41 "0" R0603-PHILLIPS 29.1,45.8 r0 bottom
R42 "0" R0603-PHILLIPS 29.1,52.9 r0 bottom
R43 "100" R0603-PHILLIPS 28.3,40.8 r270 bottom
R44 "56" R0603-PHILLIPS 29.2,55.4 r0 bottom
R45 "51" R0603-PHILLIPS 23,58 r270 bottom
R46 "10k" R0603-PHILLIPS 27.6,38.7 r180 bottom
R47 "51" R0603-PHILLIPS 21.6,58 r270 bottom
R48 "51" R0603-PHILLIPS 19.4,50.1 r0 bottom
R49 "51" R0603-PHILLIPS 19.4,52.8 r0 bottom
R50 "51" R0603-PHILLIPS 19.4,48.7 r0 bottom
R51 "51" R0603-PHILLIPS 19.4,45.8 r0 bottom
R52 "??" R0603-PHILLIPS 38.3,57.2 r270 top
R53 "??" R0603-PHILLIPS 37.1,57.2 r270 top
R54 "??" R0603-PHILLIPS 35.9,57.2 r270 top
R55 "330" R0603-PHILLIPS 33.75,43 r0 top
R56 "330" R0603-PHILLIPS 39.5,57.2 r270 top
R57 "330" R0603-PHILLIPS 33.75,40.3 r0 top
R58 "51" R0603-PHILLIPS 23,40.8 r90 bottom
R59 "51" R0603-PHILLIPS 21.6,40.8 r90 bottom
R60 "6k34" R0603-PHILLIPS 31.3,49.5 r180 bottom
R61 "1k00" R0603-PHILLIPS 36.55,42.65 r180 bottom
R62 "??" R0603-PHILLIPS 35.45,64.25 r270 top
R63 "330" R0603-PHILLIPS 26.55,59.8 r270 top
R64 "1k" R0603-PHILLIPS 35.5,61.45 r270 top
R65 "1k" R0603-PHILLIPS 149.35,95.7 r0 top
R66 "10k" R0603-PHILLIPS 158.45,109.65 r270 top
R67 "1k5" R0603-PHILLIPS 62.75,51.25 r180 bottom
R78 "1k" R0603-PHILLIPS 25.2,59.8 r90 top
R90 "33" R0603-PHILLIPS 45.15,42.35 r180 top
R91 "2k" R0603-PHILLIPS 39.3,42.65 r180 bottom
R92 "2k" R0603-PHILLIPS 40.1,44.287 r180 bottom
R93 "4k7" R0603-PHILLIPS 75.35,34.6 r0 bottom
R94 "1k" R0603-PHILLIPS 79.35,57.75 r180 top
R95-1 "1k" R0603-PHILLIPS 131.157,22.088 r0 bottom (schematic designator R95)
R95-2 "1k" R0603-PHILLIPS 131.196,71.38 r0 bottom (schematic designator R95)
R96-1 "120" R0603-PHILLIPS 145.739,13.152 r0 top (schematic designator R96)
R96-2 "120" R0603-PHILLIPS 145.55,62.8 r0 top (schematic designator R96)
R97-1 "56" R0603-PHILLIPS 145.95,21.95 r0 top (schematic designator R97)
R97-2 "56" R0603-PHILLIPS 146.54,72.226 r270 top (schematic designator R97)
R98-1 "56" R0603-PHILLIPS 146,39.7 r0 top (schematic designator R98)
R98-2 "56" R0603-PHILLIPS 146.552,88.522 r270 top (schematic designator R98)
R99-1 "120" R0603-PHILLIPS 146.584,11.116 r270 top (schematic designator R99)
R99-2 "120" R0603-PHILLIPS 146.3,60.75 r270 top (schematic designator R99)
R100-1 "120" R0603-PHILLIPS 146.59,19.827 r270 top (schematic designator R100)
R100-2 "120" R0603-PHILLIPS 146.54,69.326 r270 top (schematic designator R100)
R101-1 "120" R0603-PHILLIPS 146.542,36.556 r270 top (schematic designator R101)
R101-2 "120" R0603-PHILLIPS 146.552,85.75 r270 top (schematic designator R101)
R102-1 "270" R0603-PHILLIPS 117.311,19.658 r0 bottom (schematic designator R102)
R102-2 "270" R0603-PHILLIPS 117.35,68.95 r0 bottom (schematic designator R102)
R103-1 "270" R0603-PHILLIPS 119.461,13.858 r90 top (schematic designator R103)
R103-2 "270" R0603-PHILLIPS 119.5,63.15 r90 top (schematic designator R103)
R104-1 "150" R0603-PHILLIPS 131.157,19.738 r180 bottom (schematic designator R104)
R104-2 "150" R0603-PHILLIPS 131.196,69.03 r180 bottom (schematic designator R104)
R105-1 "10" R0603-PHILLIPS 131.161,20.508 r180 top (schematic designator R105)
R105-2 "10" R0603-PHILLIPS 131.2,69.8 r180 top (schematic designator R105)
R106-1 "820" R0603-PHILLIPS 131.107,10.538 r180 top (schematic designator R106)
R106-2 "820" R0603-PHILLIPS 131.146,59.83 r180 top (schematic designator R106)
R107-1 "390" R0603-PHILLIPS 118.211,13.858 r270 bottom (schematic designator R107)
R107-2 "390" R0603-PHILLIPS 118.25,63.15 r270 bottom (schematic designator R107)
R108-1 "12k" R0603-PHILLIPS 131.211,28.408 r180 top (schematic designator R108)
R108-2 "12k" R0603-PHILLIPS 131.225,77.875 r180 top (schematic designator R108)
R109-1 "1k2" R0603-PHILLIPS 131.107,12.988 r180 top (schematic designator R109)
R109-2 "1k2" R0603-PHILLIPS 131.146,62.28 r180 top (schematic designator R109)
R110-1 "51" R0603-PHILLIPS 130.361,9.158 r180 bottom (schematic designator R110)
R110-2 "51" R0603-PHILLIPS 130.4,58.45 r180 bottom (schematic designator R110)
R111-1 "51" R0603-PHILLIPS 130.357,10.288 r180 bottom (schematic designator R111)
R111-2 "51" R0603-PHILLIPS 130.396,59.58 r180 bottom (schematic designator R111)
R112-1 "51" R0603-PHILLIPS 130.357,11.588 r180 bottom (schematic designator R112)
R112-2 "51" R0603-PHILLIPS 130.396,60.88 r180 bottom (schematic designator R112)
R113-1 "51" R0603-PHILLIPS 130.357,12.888 r180 bottom (schematic designator R113)
R113-2 "51" R0603-PHILLIPS 130.396,62.18 r180 bottom (schematic designator R113)
R114-1 "6k8" R0603-PHILLIPS 119.461,13.858 r90 bottom (schematic designator R114)
R114-2 "6k8" R0603-PHILLIPS 119.5,63.15 r90 bottom (schematic designator R114)
R115-1 "0" R0603-PHILLIPS 116.611,27.208 r90 top (schematic designator R115)
R115-2 "0" R0603-PHILLIPS 116.65,76.5 r90 top (schematic designator R115)
R116-1 "0" R0603-PHILLIPS 115.461,27.208 r90 top (schematic designator R116)
R116-2 "0" R0603-PHILLIPS 115.5,76.5 r90 top (schematic designator R116)
R117-1 "0" R0603-PHILLIPS 119.011,27.208 r90 top (schematic designator R117)
R117-2 "0" R0603-PHILLIPS 118.95,76.5 r90 top (schematic designator R117)
R118-1 "0" R0603-PHILLIPS 117.761,27.208 r90 top (schematic designator R118)
R118-2 "0" R0603-PHILLIPS 117.8,76.5 r90 top (schematic designator R118)
R119-1 "1k2" R0603-PHILLIPS 131.161,23.258 r180 bottom (schematic designator R119)
R119-2 "1k2" R0603-PHILLIPS 131.2,72.55 r180 bottom (schematic designator R119)
R120-1 "2k2" R0603-PHILLIPS 116.661,27.208 r90 bottom (schematic designator R120)
R120-2 "2k2" R0603-PHILLIPS 116.7,76.5 r90 bottom (schematic designator R120)
R121-1 "820" R0603-PHILLIPS 133.461,25.008 r270 bottom (schematic designator R121)
R121-2 "820" R0603-PHILLIPS 133.5,74.3 r270 bottom (schematic designator R121)
R122-1 "2k2" R0603-PHILLIPS 115.461,27.208 r270 bottom (schematic designator R122)
R122-2 "2k2" R0603-PHILLIPS 115.5,76.5 r270 bottom (schematic designator R122)
R123-1 "2k2" R0603-PHILLIPS 119.161,27.208 r90 bottom (schematic designator R123)
R123-2 "2k2" R0603-PHILLIPS 119.2,76.5 r90 bottom (schematic designator R123)
R124-1 "2k2" R0603-PHILLIPS 117.961,27.208 r270 bottom (schematic designator R124)
R124-2 "2k2" R0603-PHILLIPS 118,76.5 r270 bottom (schematic designator R124)
R125-1 "??" R0603-PHILLIPS 124.061,27.108 r270 top (schematic designator R125)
